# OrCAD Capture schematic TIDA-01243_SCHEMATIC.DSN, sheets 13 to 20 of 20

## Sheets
13 PAGE13_DP4320: size B; title: TIDA-01243: DP4320; rev: B
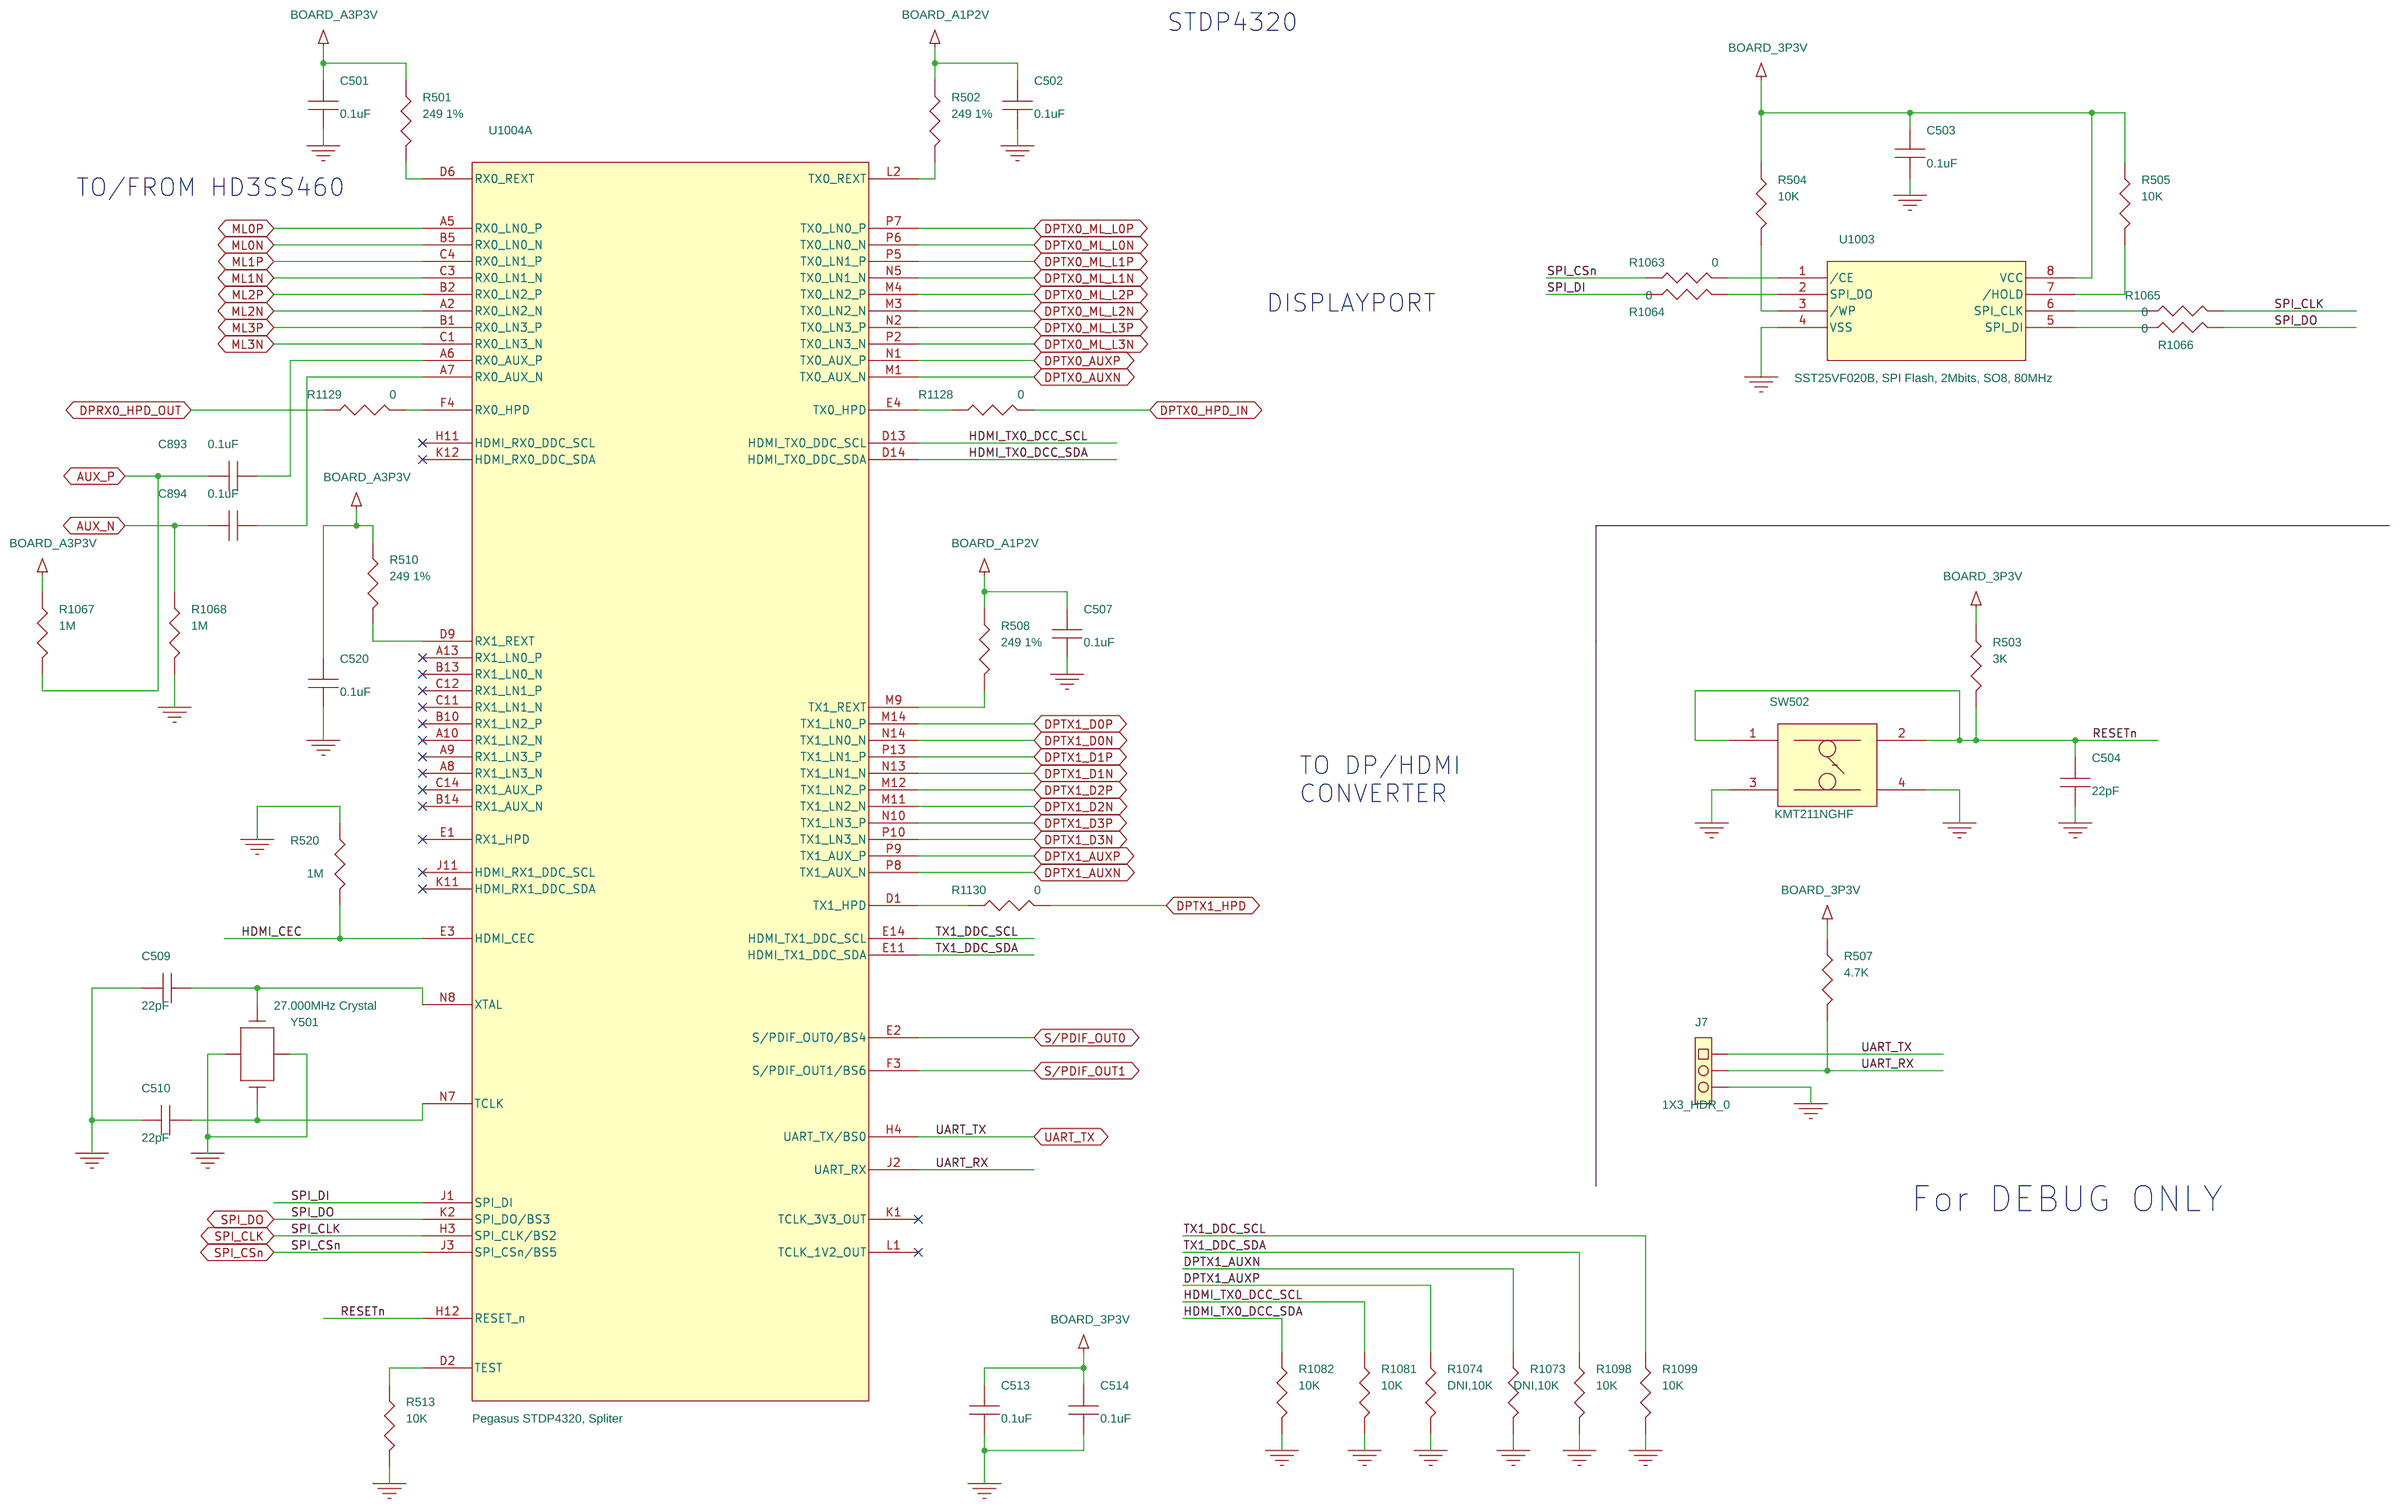
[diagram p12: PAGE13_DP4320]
14 PAGE14_DP4320_POWER: size B; title: TIDA-01243: DP4320 POWER; rev: B
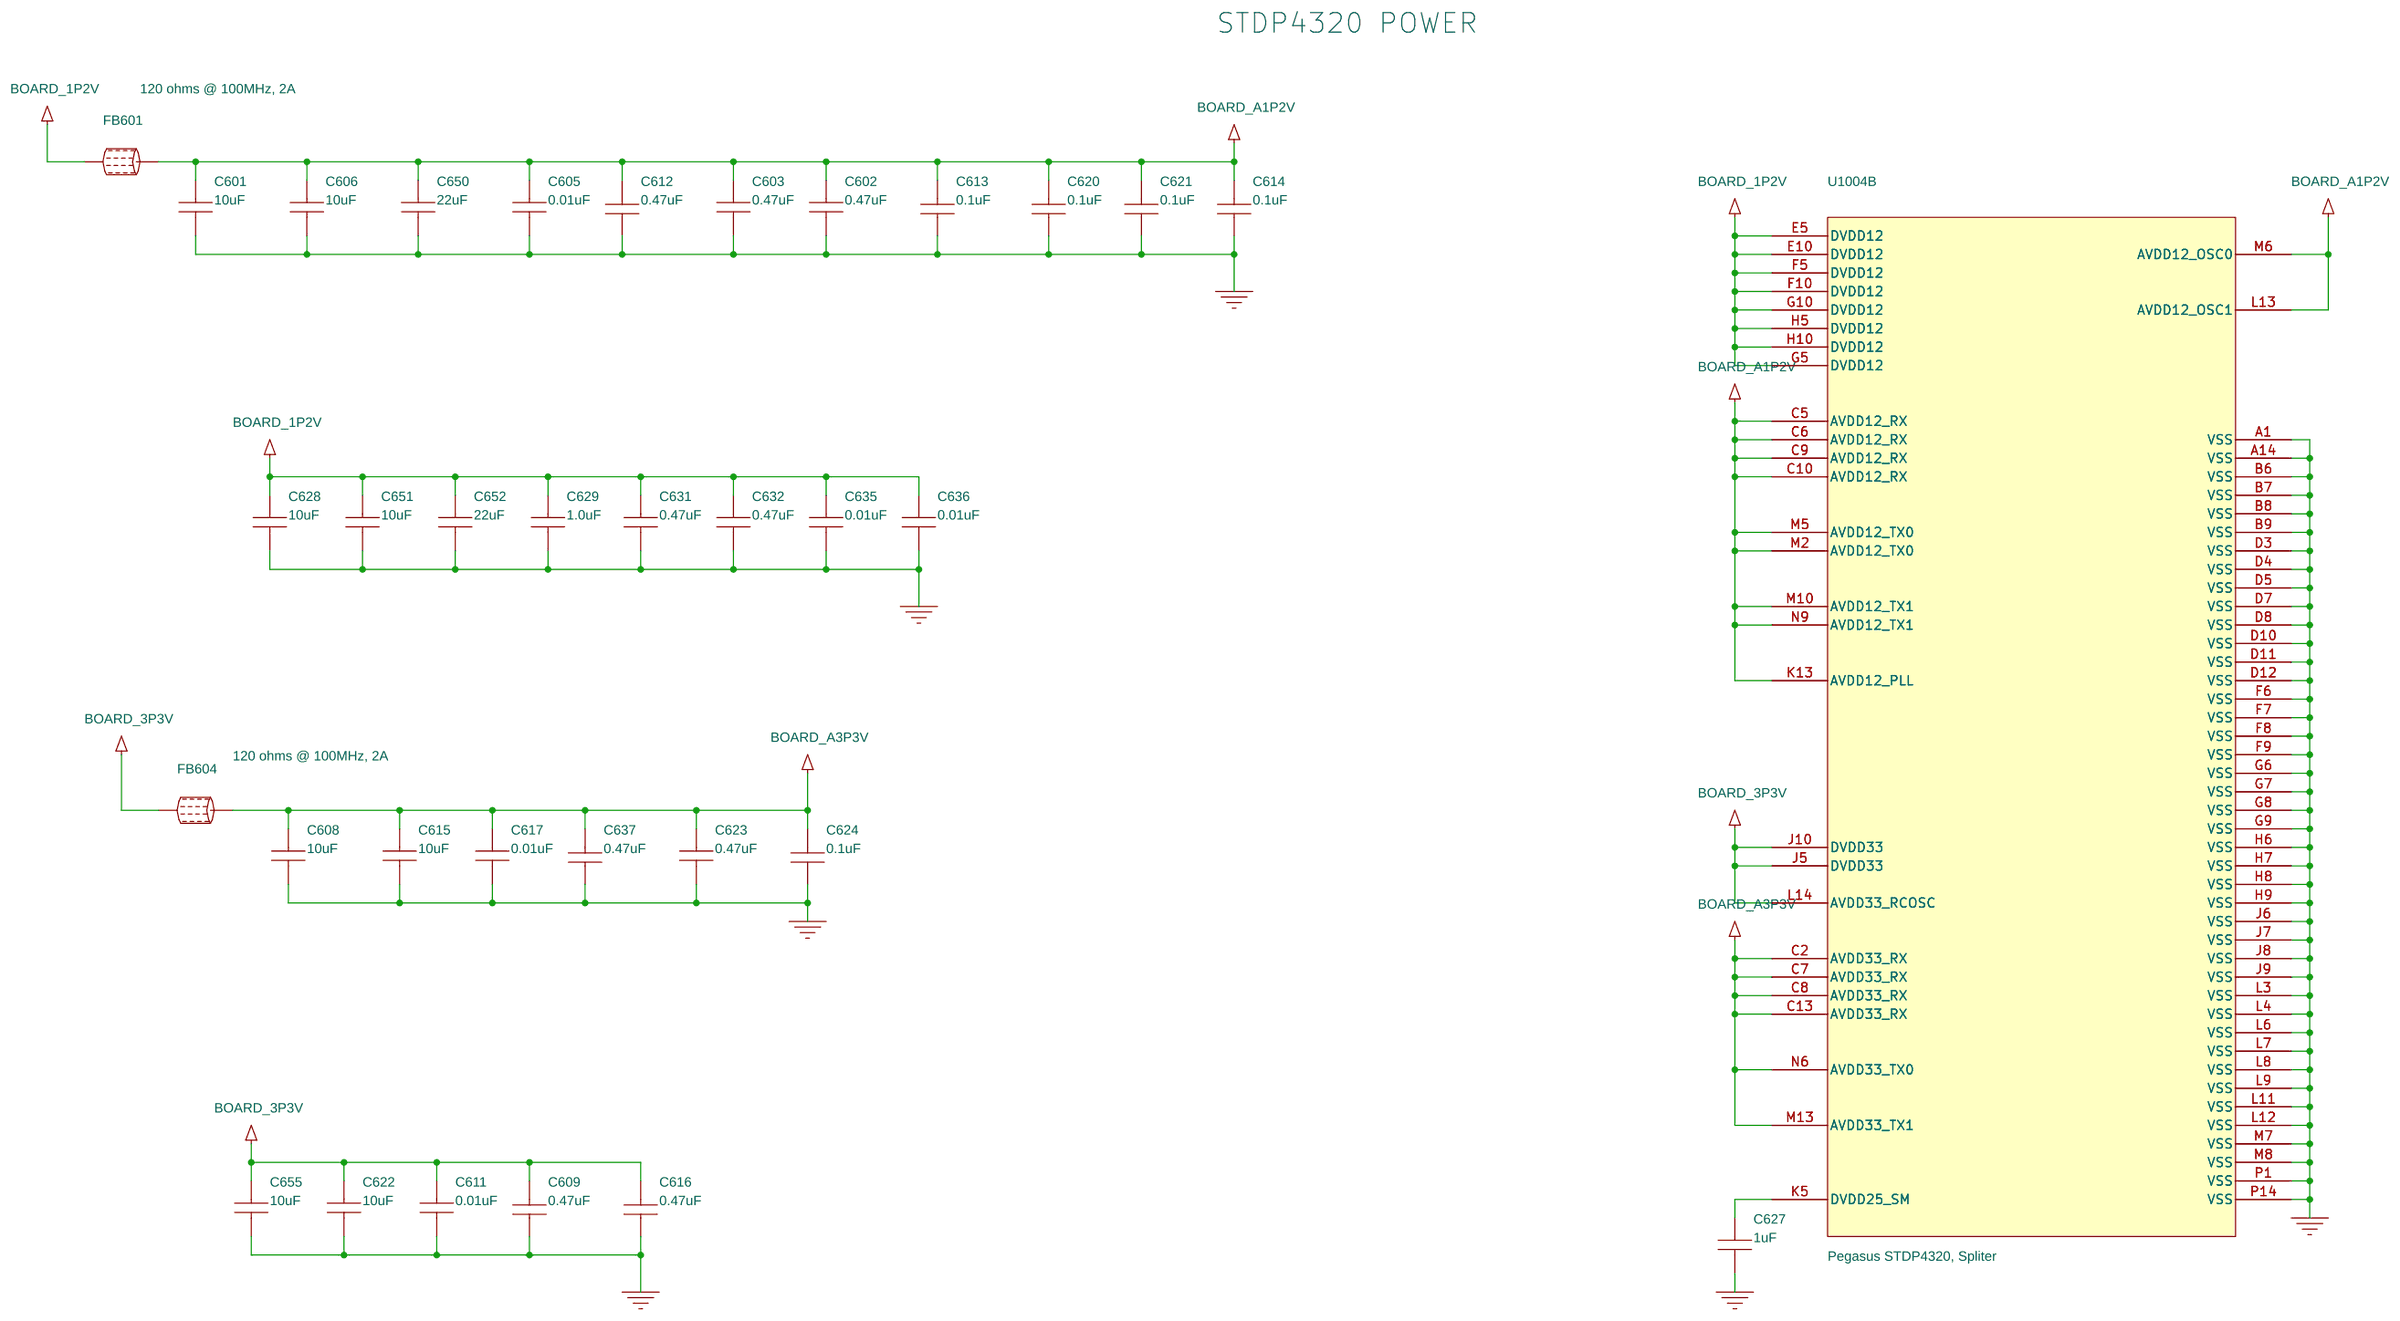
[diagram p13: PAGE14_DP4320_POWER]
15 PAGE15_DP4320_BOOTSTRAP: size B; title: TIDA-01243: DP4320 BOOTSTRAP; rev: B
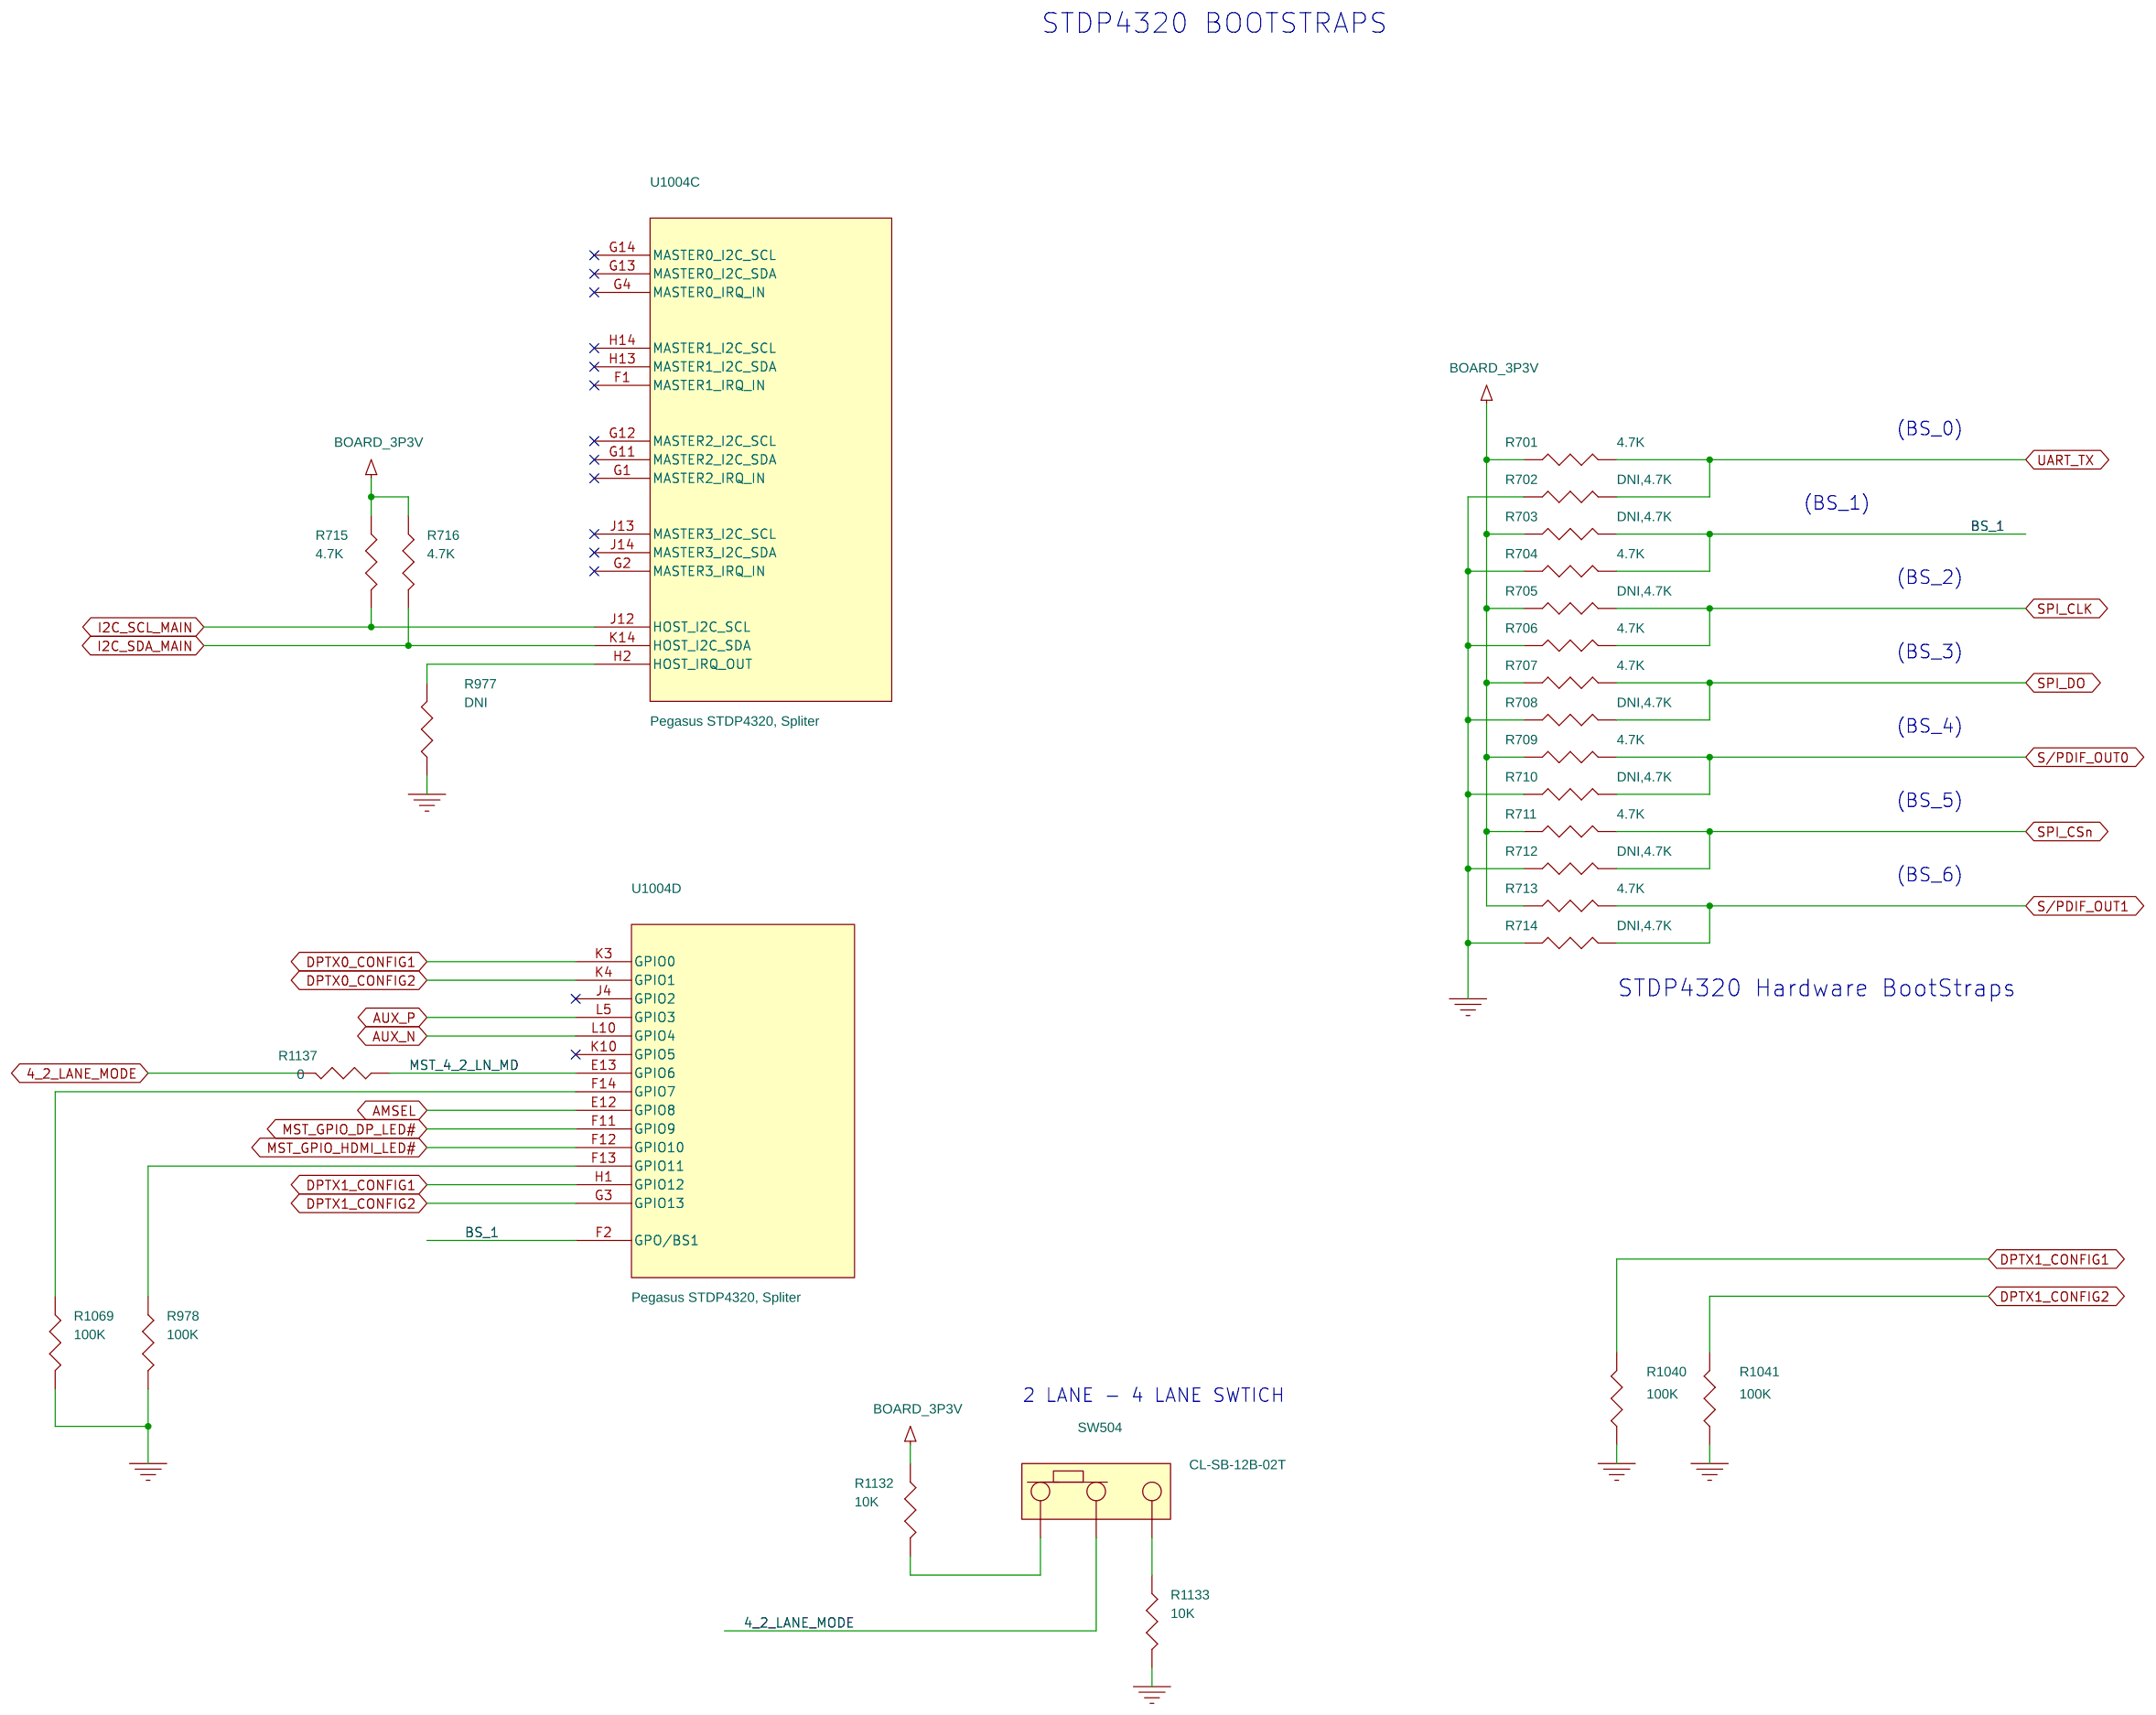
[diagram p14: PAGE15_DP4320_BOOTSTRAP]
16 PAGE16_DISPLAYPORT: size B; title: TIDA-01243: DISPLAY PORT; rev: B
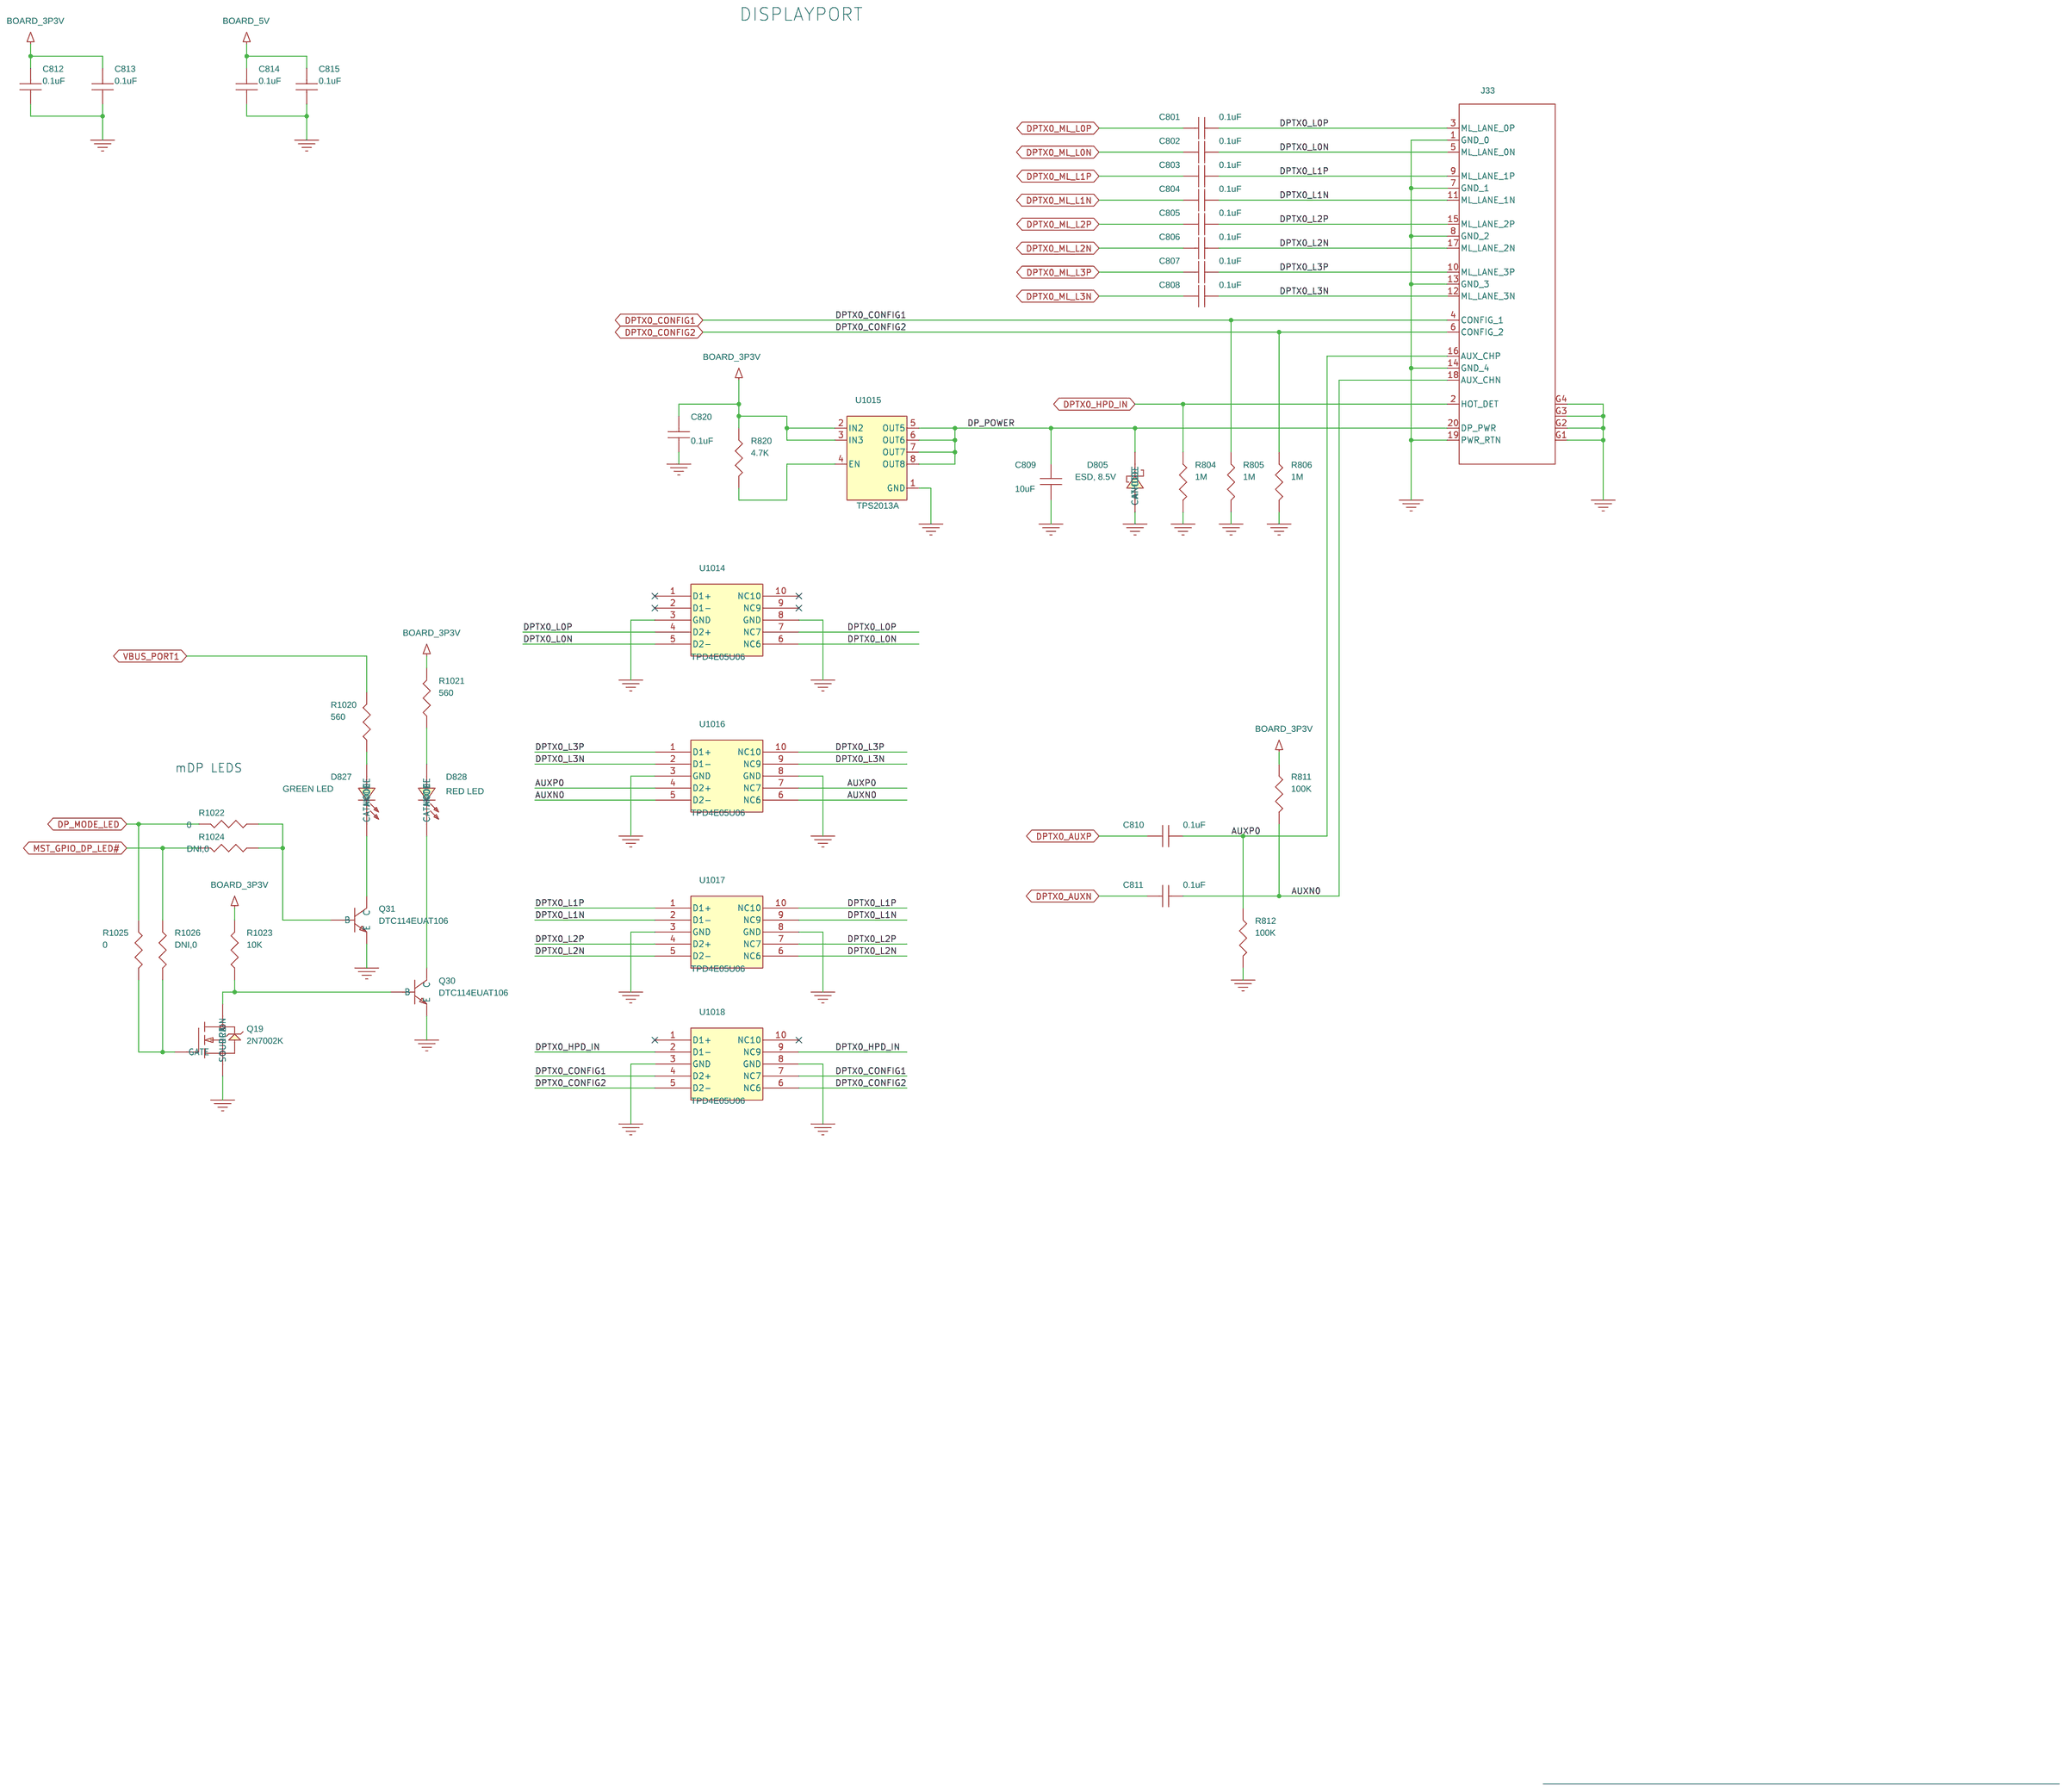
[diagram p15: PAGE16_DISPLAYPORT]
17 PAGE17_DP_TO_HDMI: size B; title: TIDA-01243: dDP TO HDMI; rev: B
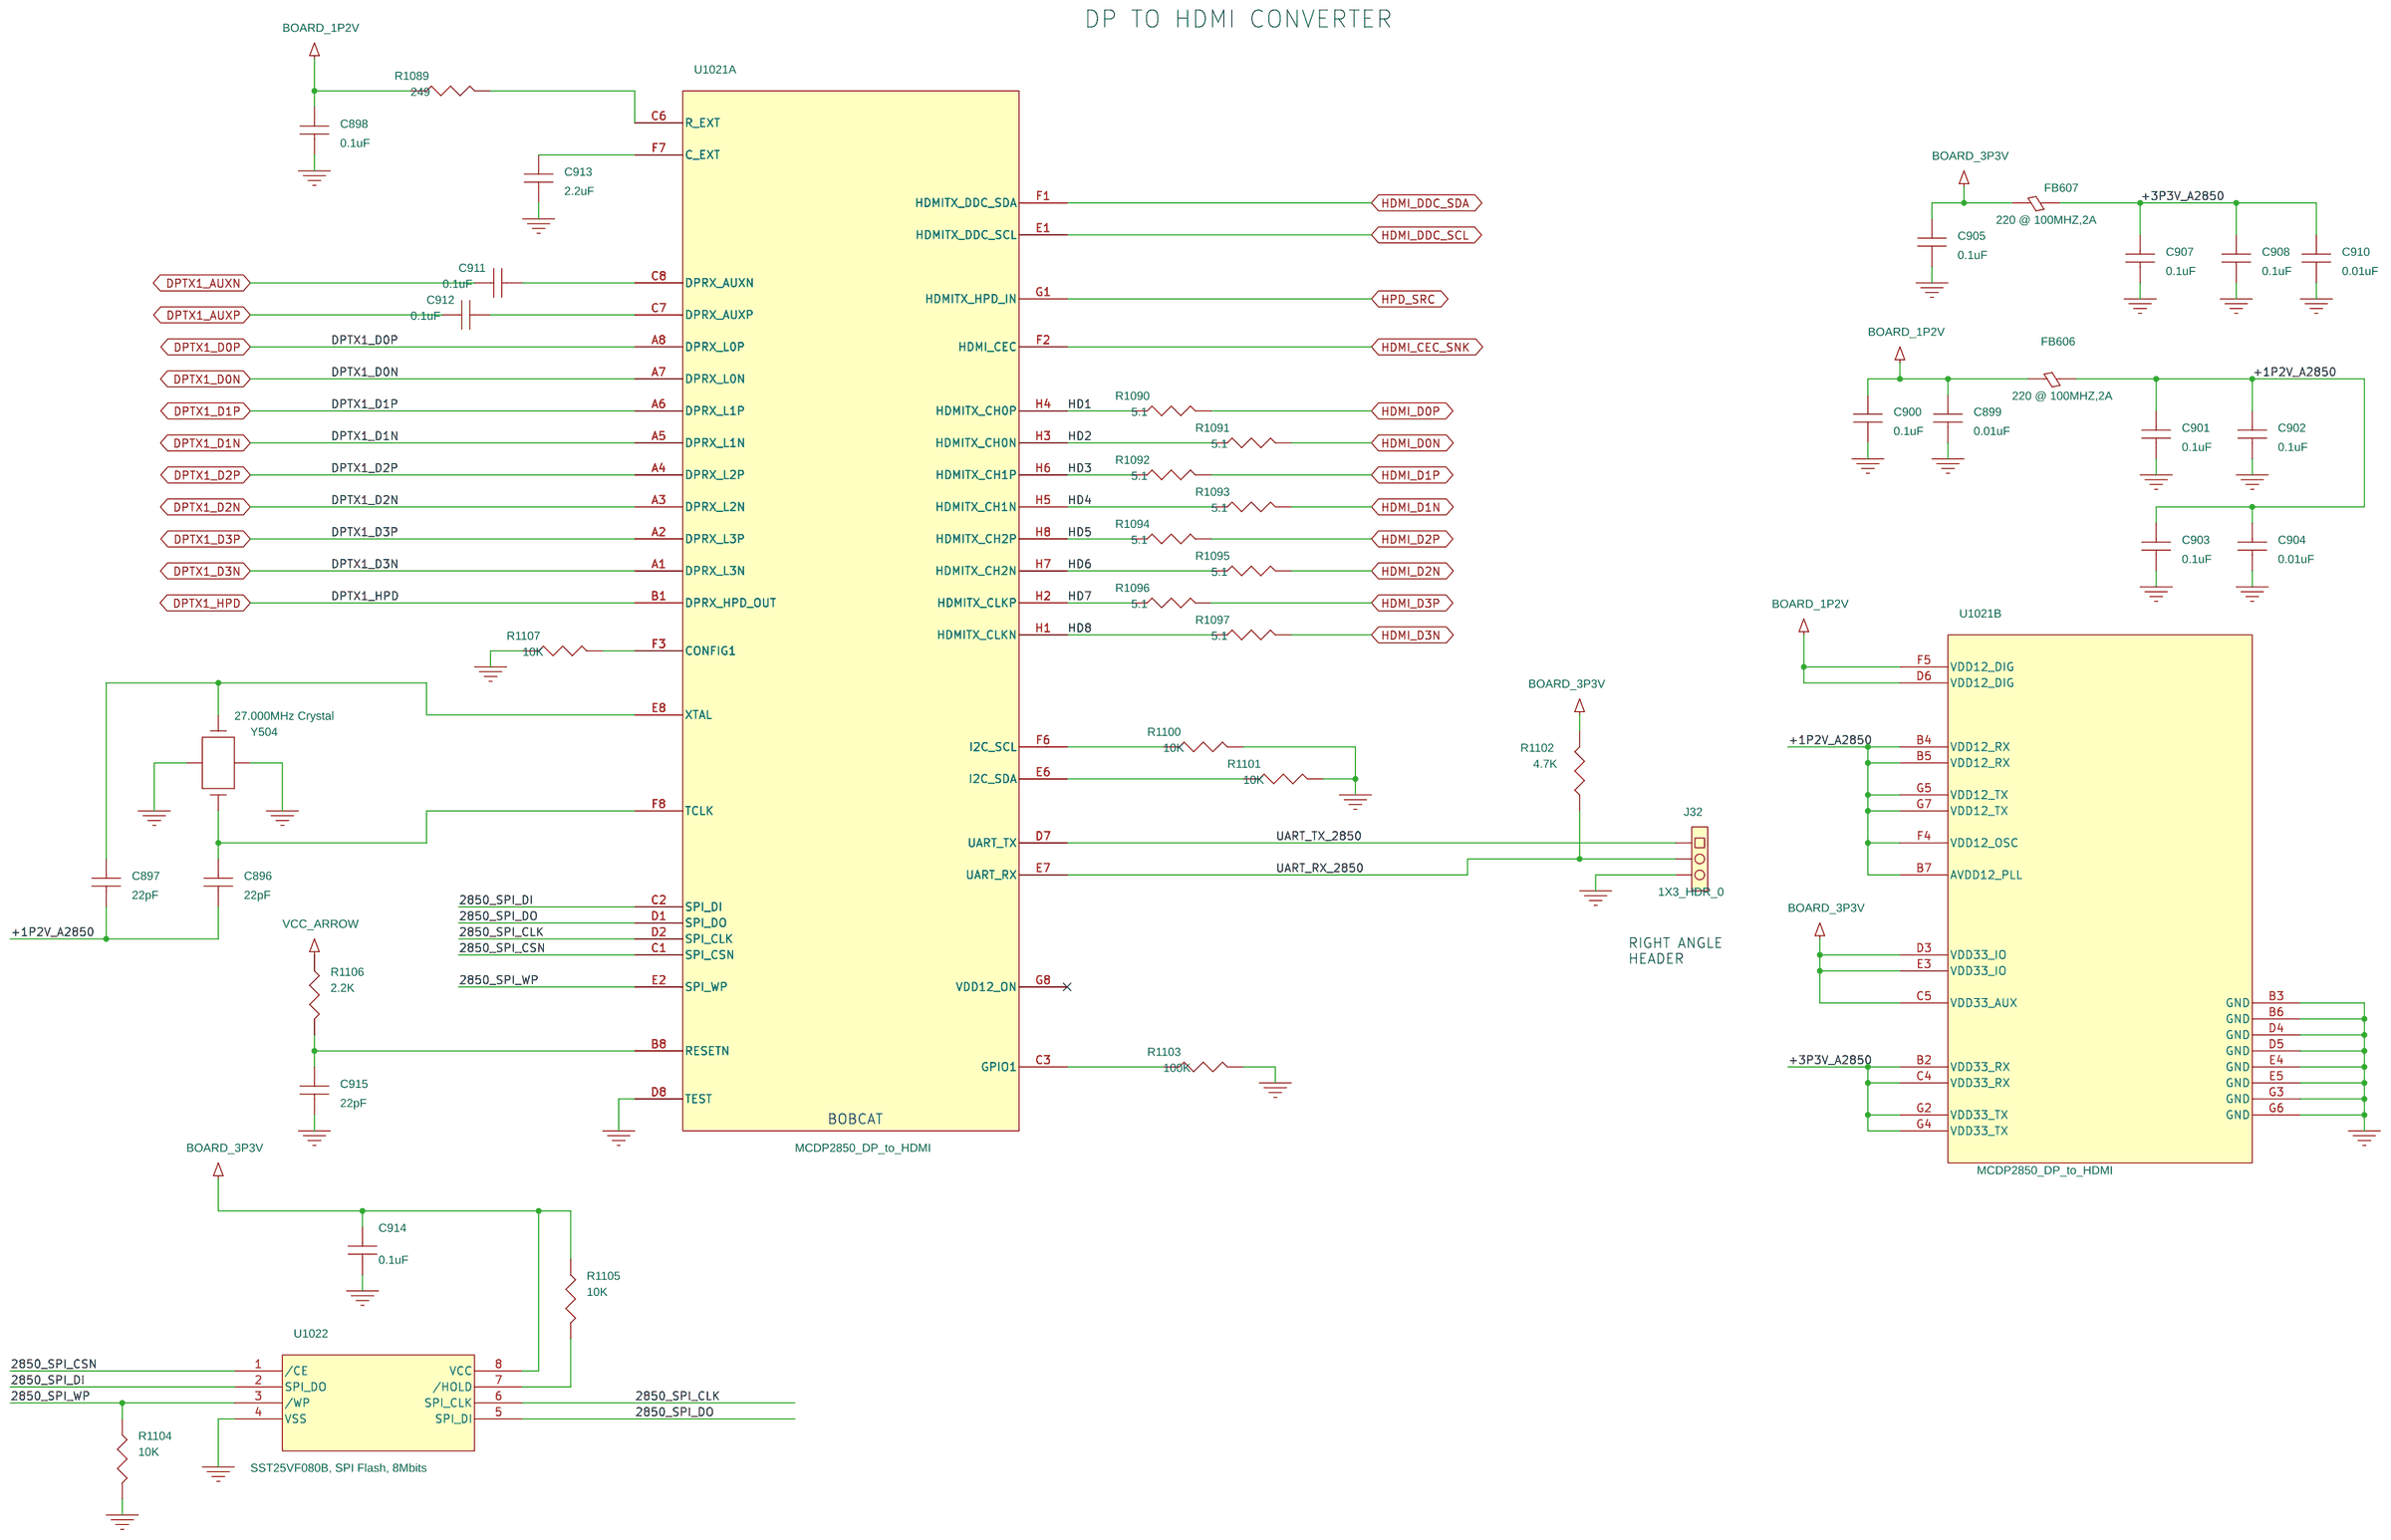
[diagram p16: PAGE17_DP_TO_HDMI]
18 PAGE18_HDMI_CONNECTOR: size B; title: TIDA-01243: HDMI CONNECTOR; rev: B
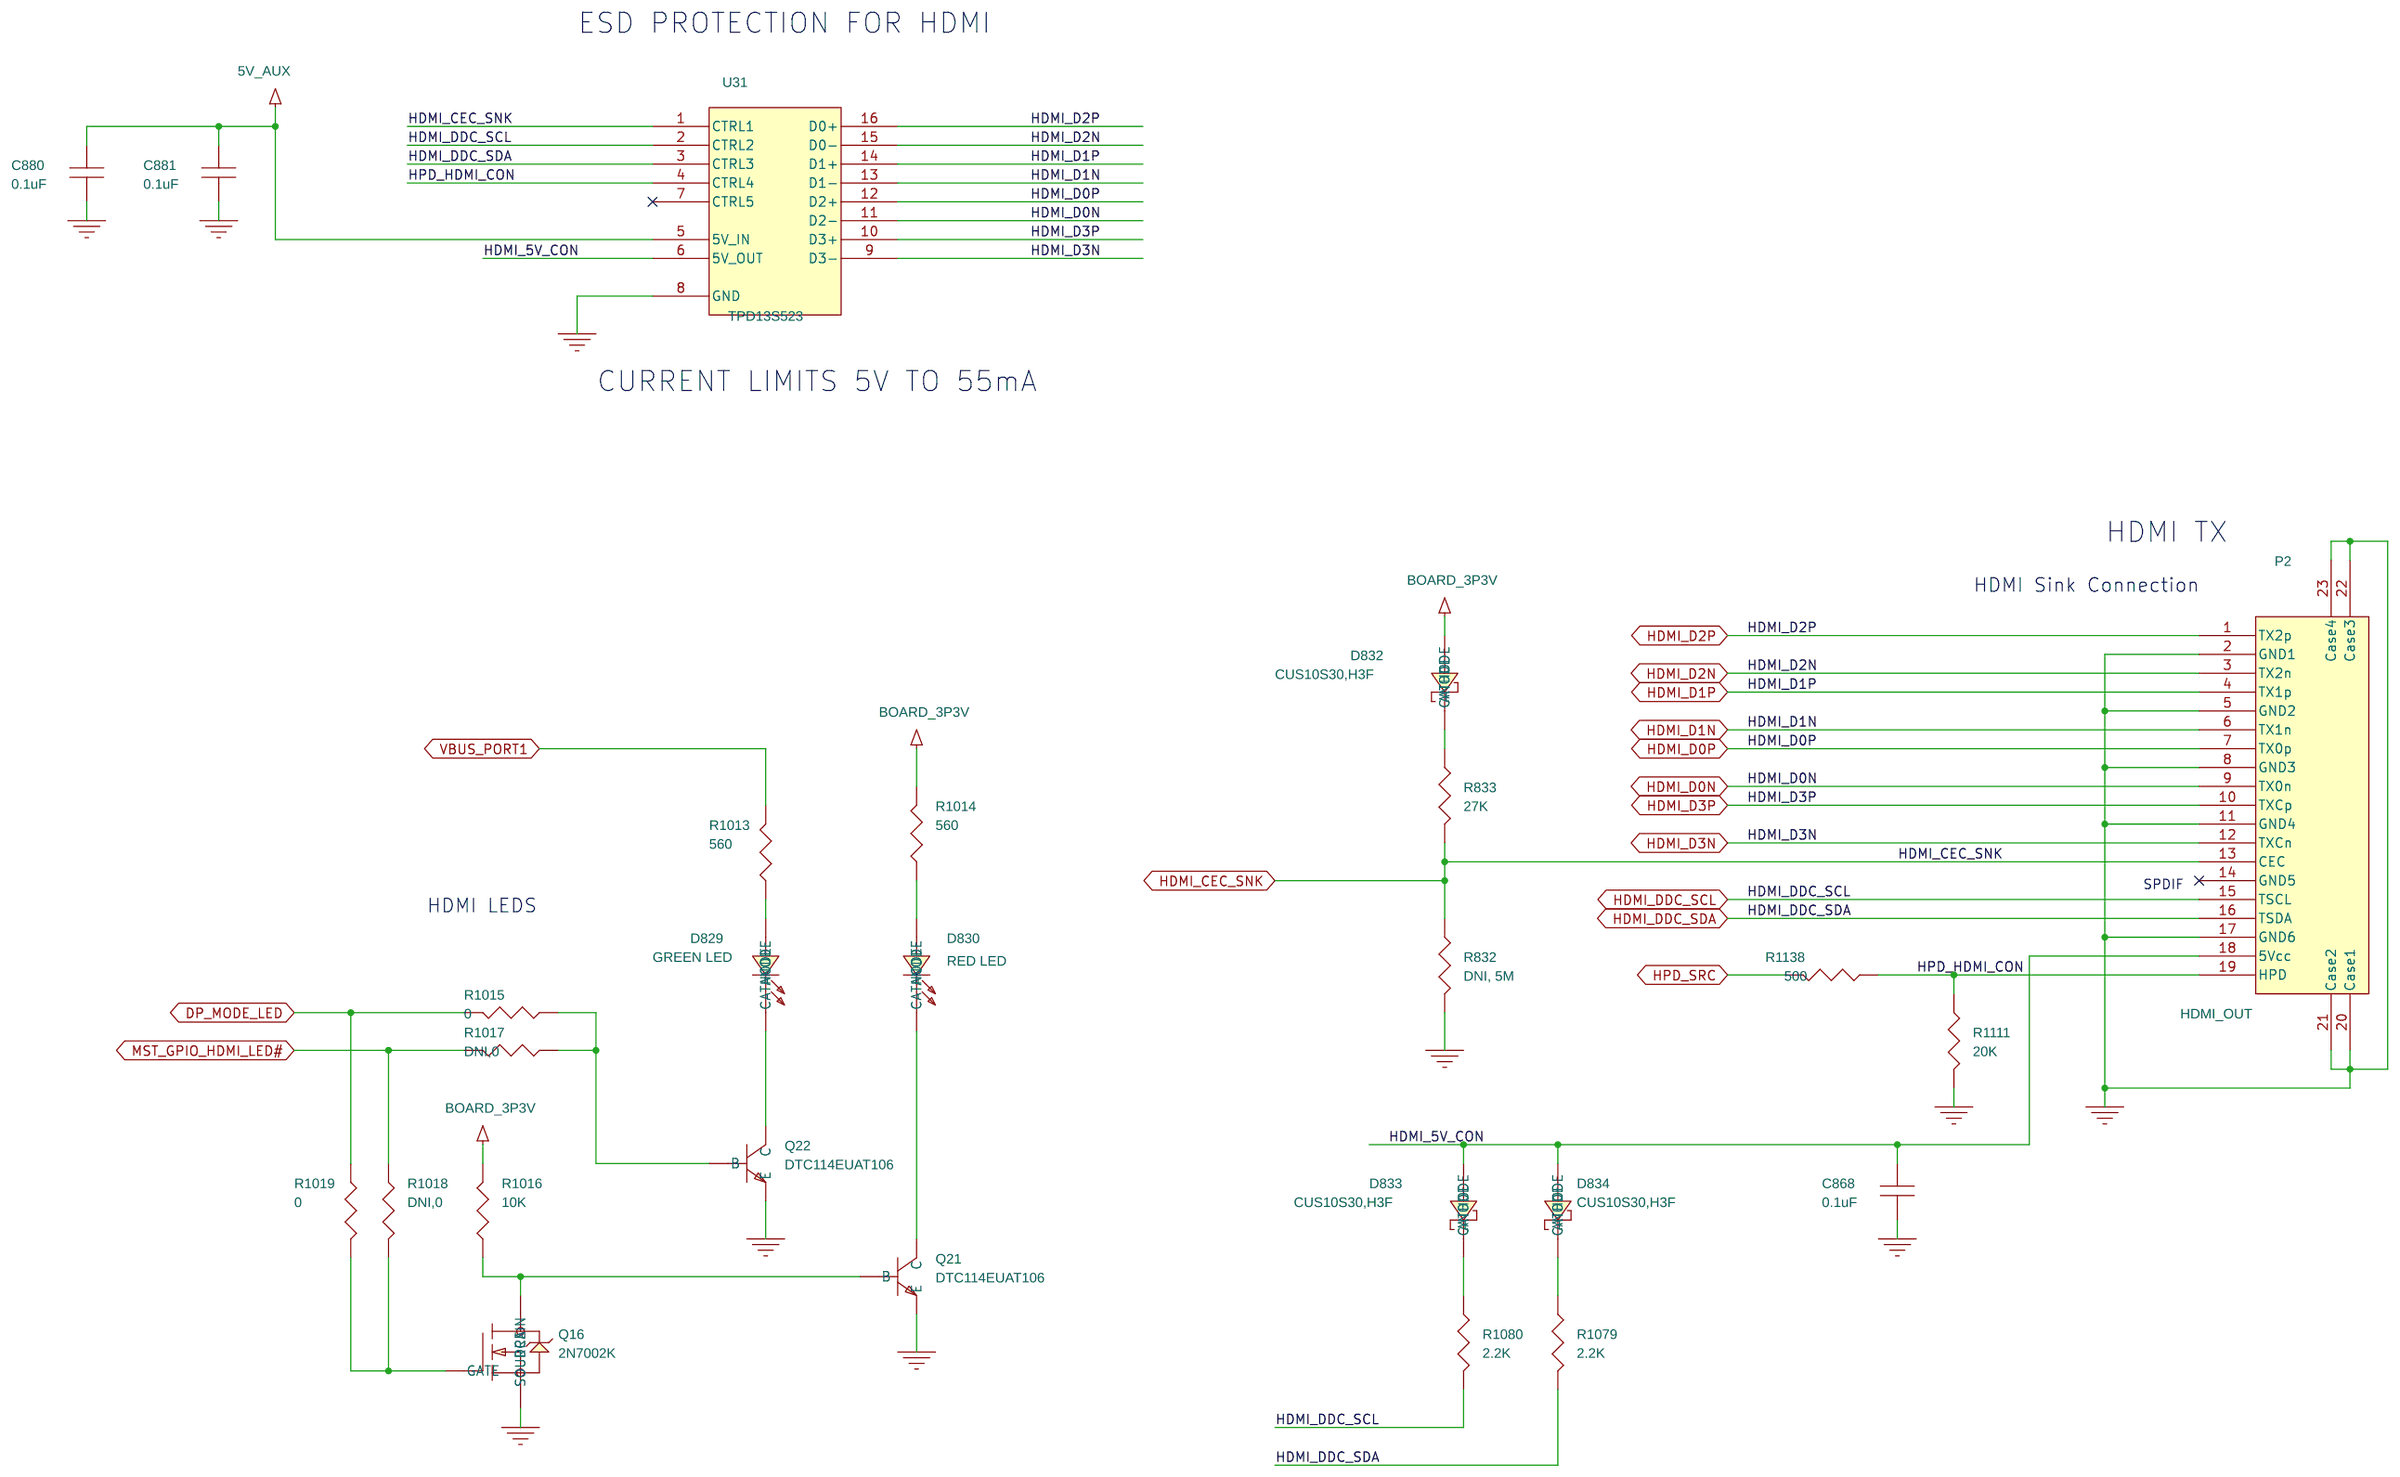
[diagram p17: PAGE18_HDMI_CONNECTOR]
19 PAGE19_DEBUG_BOARD: size B; title: TIDA-01243: Debug Board; rev: B
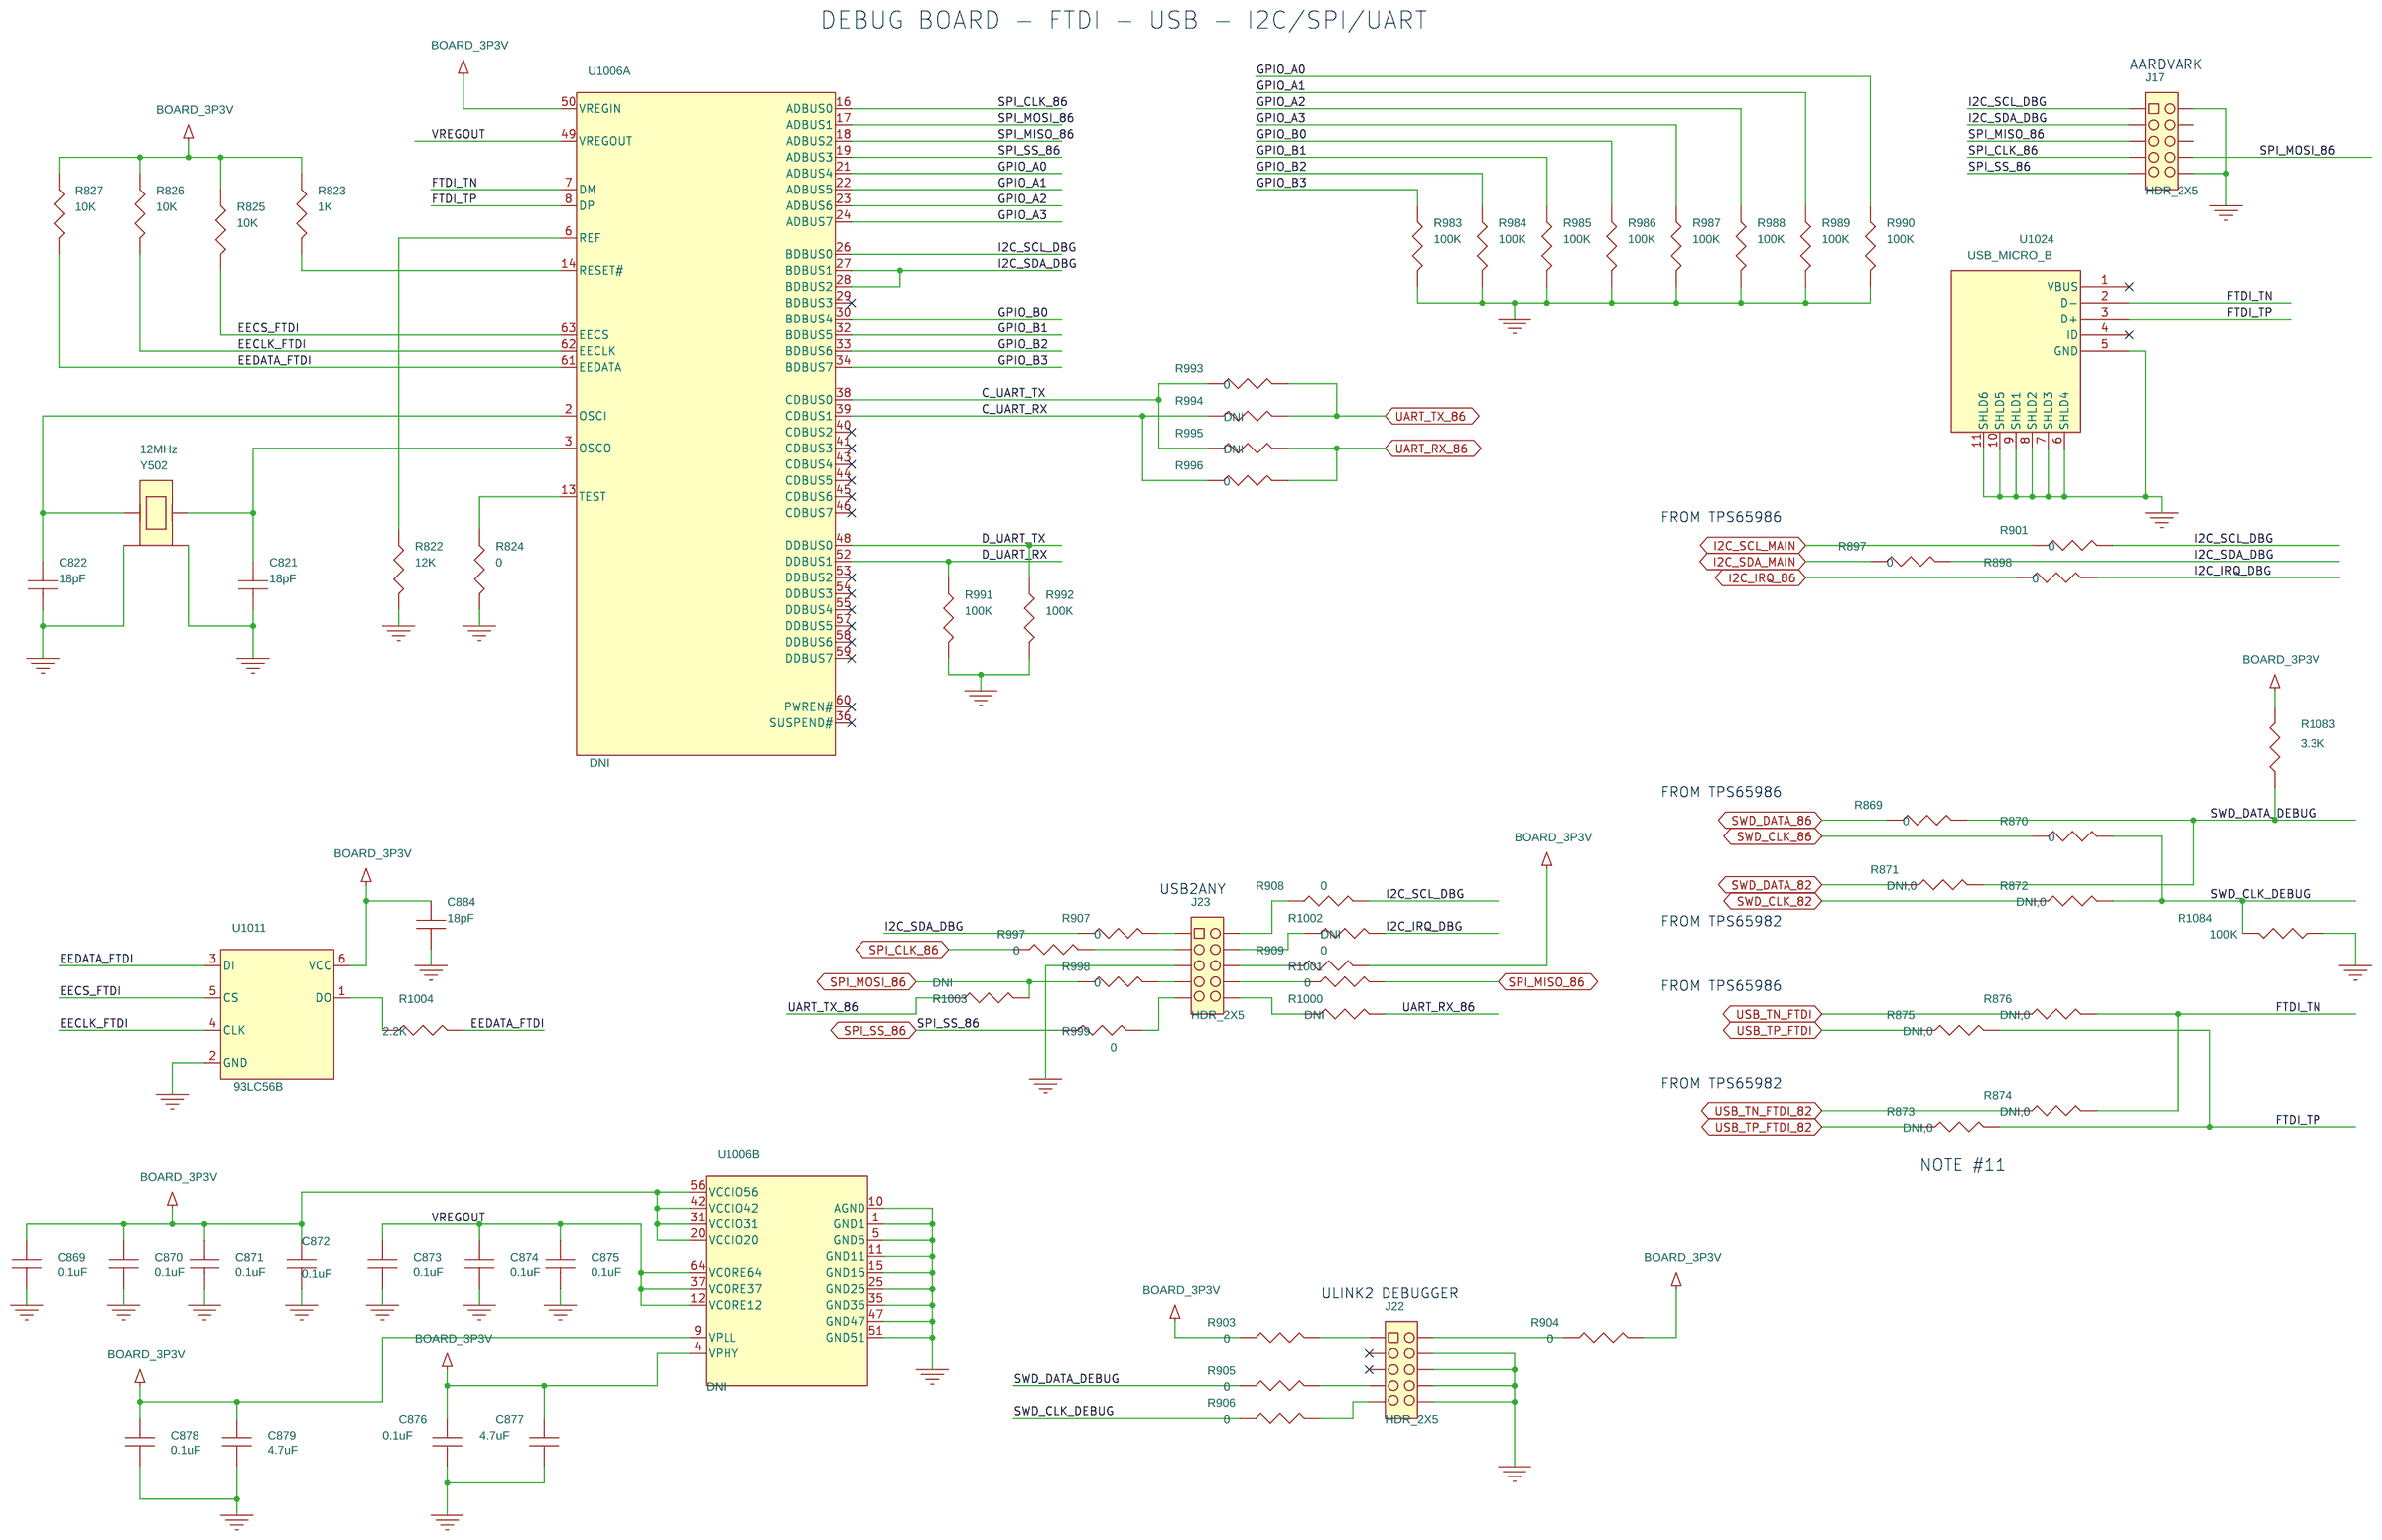
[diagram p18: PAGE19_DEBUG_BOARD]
20 PAGE04_USB_TYPEC_UP/HD3SS460: size B; title: TIDA-01243: USB TYPE-C; rev: B
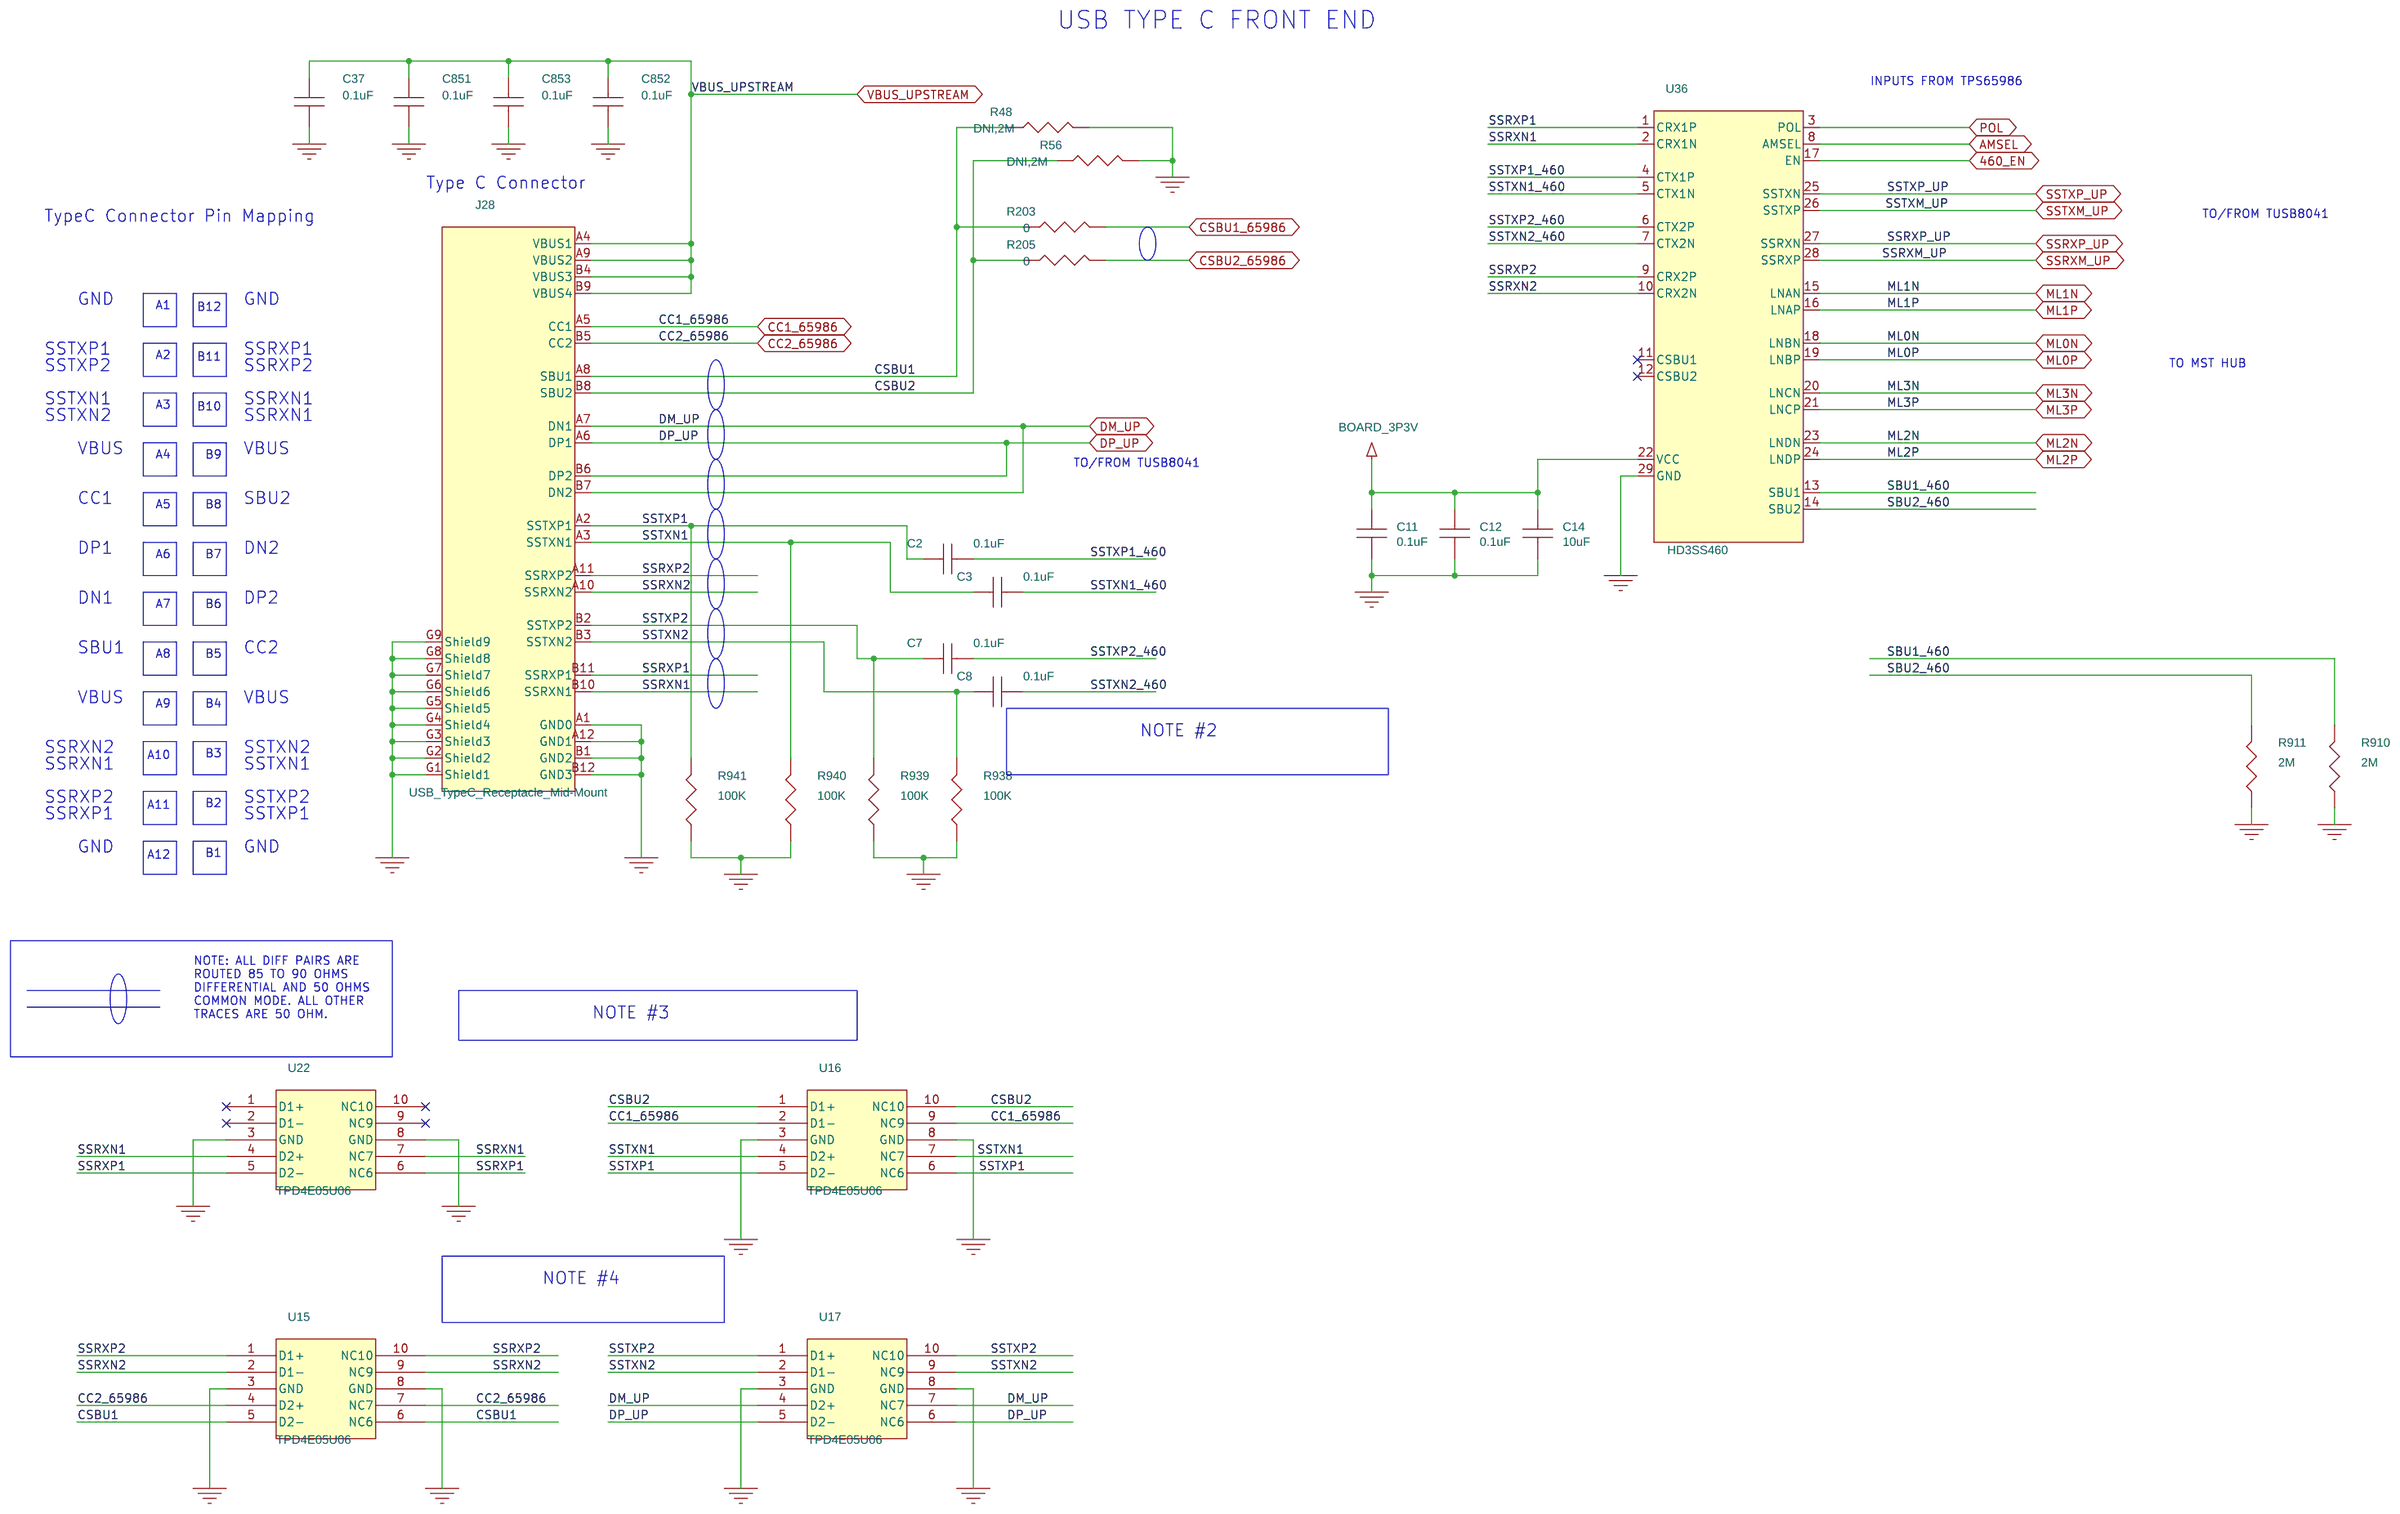
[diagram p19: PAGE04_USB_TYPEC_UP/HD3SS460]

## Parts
sheet PAGE04_USB_TYPEC_UP/HD3SS460
C2  0.1uF  [0201RND]
C3  0.1uF  [0201RND]
C7  0.1uF  [0201RND]
C8  0.1uF  [0201RND]
C11  0.1uF  [C0402]
C12  0.1uF  [C0402]
C14  10uF  [C0402]
C37  0.1uF  [C0402]
C851  0.1uF  [C0402]
C852  0.1uF  [C0402]
C853  0.1uF  [C0402]
J28  USB_TypeC_Receptacle_Mid-Mount  [USB_typeC_20-0000016-01]
R48  DNI,2M  [0201RND]
R56  DNI,2M  [0201RND]
R203  0  [0201RND]
R205  0  [0201RND]
R910  2M  [R0402]
R911  2M  [R0402]
R938  100K  [0201RND]
R939  100K  [0201RND]
R940  100K  [0201RND]
R941  100K  [0201RND]
U15  TPD4E05U06  [DQA]
U16  TPD4E05U06  [DQA]
U17  TPD4E05U06  [DQA]
U22  TPD4E05U06  [DQA]
U36  HD3SS460  [RHR_R-PWQFN-N28]
sheet PAGE13_DP4320
C501  0.1uF  [C0402]
C502  0.1uF  [C0402]
C503  0.1uF  [C0402]
C504  22pF  [C0402]
C507  0.1uF  [C0402]
C509  22pF  [C0402]
C510  22pF  [C0402]
C513  0.1uF  [C0402]
C514  0.1uF  [C0402]
C520  0.1uF  [C0402]
C893  0.1uF  [C0402]
C894  0.1uF  [C0402]
J7  1X3_HDR_0  [HDR_THVT_1X3_100]
R501  249 1%  [R0402]
R502  249 1%  [R0402]
R503  3K  [R0402]
R504  10K  [R0402]
R505  10K  [R0402]
R507  4.7K  [R0603]
R508  249 1%  [R0402]
R510  249 1%  [R0402]
R513  10K  [R0402]
R520  1M  [R0603]
R1063  0  [R0402]
R1064  0  [R0402]
R1065  0  [R0402]
R1066  0  [R0402]
R1067  1M  [R0402]
R1068  1M  [R0402]
R1073  DNI,10K  [R0402]
R1074  DNI,10K  [R0402]
R1081  10K  [R0402]
R1082  10K  [R0402]
R1098  10K  [R0402]
R1099  10K  [R0402]
R1128  0  [R0402]
R1129  0  [R0402]
R1130  0  [R0402]
SW502  KMT211NGHF  [SW_SMVT_KTM2]
U1003  SST25VF020B, SPI Flash, 2Mbits, SO8, 80MHz  [SOIC_8_197x157_50]
Y501  27.000MHz Crystal  [XTAL_4_SM_ECX-32]
sheet PAGE14_DP4320_POWER
C601  10uF  [C0603]
C602  0.47uF  [C0402]
C603  0.47uF  [C0402]
C605  0.01uF  [C0402]
C606  10uF  [C0603]
C608  10uF  [C0603]
C609  0.47uF  [C0402]
C611  0.01uF  [C0402]
C612  0.47uF  [C0402]
C613  0.1uF  [C0402]
C614  0.1uF  [C0402]
C615  10uF  [C0603]
C616  0.47uF  [C0402]
C617  0.01uF  [C0402]
C620  0.1uF  [C0402]
C621  0.1uF  [C0402]
C622  10uF  [C0603]
C623  0.47uF  [C0402]
C624  0.1uF  [C0402]
C627  1uF  [C0402]
C628  10uF  [C0603]
C629  1.0uF  [C0402]
C631  0.47uF  [C0402]
C632  0.47uF  [C0402]
C635  0.01uF  [C0402]
C636  0.01uF  [C0402]
C637  0.47uF  [C0402]
C650  22uF  [C0603]
C651  10uF  [C0603]
C652  22uF  [C0603]
C655  10uF  [C0603]
FB601  120 ohms @ 100MHz, 2A  [FB_0603]
FB604  120 ohms @ 100MHz, 2A  [FB_0603]
sheet PAGE15_DP4320_BOOTSTRAP
R701  4.7K  [R0402]
R702  DNI,4.7K  [R0402]
R703  DNI,4.7K  [R0402]
R704  4.7K  [R0402]
R705  DNI,4.7K  [R0402]
R706  4.7K  [R0402]
R707  4.7K  [R0402]
R708  DNI,4.7K  [R0402]
R709  4.7K  [R0402]
R710  DNI,4.7K  [R0402]
R711  4.7K  [R0402]
R712  DNI,4.7K  [R0402]
R713  4.7K  [R0402]
R714  DNI,4.7K  [R0402]
R715  4.7K  [R0402]
R716  4.7K  [R0402]
R977  DNI  [R0402]
R978  100K  [R0402]
R1040  100K  [R0402]
R1041  100K  [R0402]
R1069  100K  [R0402]
R1132  10K  [R0402]
R1133  10K  [R0402]
R1137  0  [R0402]
SW504  CL-SB-12B-02T  [SW_SMVT_CL-SB-12B-02]
U1004  Pegasus STDP4320, Spliter  [BGA_172_472X472_p80mm]  (sections A,B,C,D)
sheet PAGE16_DISPLAYPORT
C801  0.1uF  [C0402]
C802  0.1uF  [C0402]
C803  0.1uF  [C0402]
C804  0.1uF  [C0402]
C805  0.1uF  [C0402]
C806  0.1uF  [C0402]
C807  0.1uF  [C0402]
C808  0.1uF  [C0402]
C809  10uF  [C0603]
C810  0.1uF  [C0402]
C811  0.1uF  [C0402]
C812  0.1uF  [C0402]
C813  0.1uF  [C0402]
C814  0.1uF  [C0402]
C815  0.1uF  [C0402]
C820  0.1uF  [C0402]
D805  ESD, 8.5V  [Diode_ST0201]
D827  GREEN LED  [LED_0603]
D828  RED LED  [LED_0603]
J33  MINI_DISPLAY_PORT  [CON_RT_20_MINI_DP_JAE]
Q19  2N7002K  [SOT_23_321]
Q30  DTC114EUAT106  [SOT_323-312]
Q31  DTC114EUAT106  [SOT_323-312]
R804  1M  [R0603]
R805  1M  [R0603]
R806  1M  [R0603]
R811  100K  [R0402]
R812  100K  [R0402]
R820  4.7K  [R0402]
R1020  560  [R0402]
R1021  560  [R0402]
R1022  0  [R0402]
R1023  10K  [R0402]
R1024  DNI,0  [R0402]
R1025  0  [R0402]
R1026  DNI,0  [R0402]
U1014  TPD4E05U06  [DQA]
U1015  TPS2013A  [SOIC8]
U1016  TPD4E05U06  [DQA]
U1017  TPD4E05U06  [DQA]
U1018  TPD4E05U06  [DQA]
sheet PAGE17_DP_TO_HDMI
C896  22pF  [C0402]
C897  22pF  [C0402]
C898  0.1uF  [C0402]
C899  0.01uF  [C0402]
C900  0.1uF  [C0402]
C901  0.1uF  [C0402]
C902  0.1uF  [C0402]
C903  0.1uF  [C0402]
C904  0.01uF  [C0402]
C905  0.1uF  [C0402]
C907  0.1uF  [C0402]
C908  0.1uF  [C0402]
C910  0.01uF  [C0402]
C911  0.1uF  [C0402]
C912  0.1uF  [C0402]
C913  2.2uF  [C0402]
C914  0.1uF  [C0402]
C915  22pF  [C0402]
FB606  220 @ 100MHZ,2A  [FB_0603]
FB607  220 @ 100MHZ,2A  [FB_0603]
J32  1X3_HDR_0  [HDR_THVT_1X3_100]
R1089  249  [R0402]
R1090  5.1  [0201RND]
R1091  5.1  [0201RND]
R1092  5.1  [0201RND]
R1093  5.1  [0201RND]
R1094  5.1  [0201RND]
R1095  5.1  [0201RND]
R1096  5.1  [0201RND]
R1097  5.1  [0201RND]
R1100  10K  [R0402]
R1101  10K  [R0402]
R1102  4.7K  [R0603]
R1103  100K  [R0402]
R1104  10K  [R0402]
R1105  10K  [R0402]
R1106  2.2K  [R0402]
R1107  10K  [R0402]
U1021  MCDP2850_DP_to_HDMI  [LFBGA_64_7x7_0p8mm]  (sections A,B)
U1022  SST25VF080B, SPI Flash, 8Mbits  [SOIC_8_197x157_50]
Y504  27.000MHz Crystal  [XTAL_4_SM_ECX-32]
sheet PAGE18_HDMI_CONNECTOR
C868  0.1uF  [C0402]
C880  0.1uF  [C0402]
C881  0.1uF  [C0402]
D829  GREEN LED  [LED_0603]
D830  RED LED  [LED_0603]
D832  CUS10S30,H3F  [DIODE_SOD323]
D833  CUS10S30,H3F  [DIODE_SOD323]
D834  CUS10S30,H3F  [DIODE_SOD323]
P2  HDMI_OUT  [con_hdmi_SD-47151-001]
Q16  2N7002K  [SOT_23_321]
Q21  DTC114EUAT106  [SOT_323-312]
Q22  DTC114EUAT106  [SOT_323-312]
R832  DNI, 5M  [R0402]
R833  27K  [R0402]
R1013  560  [R0402]
R1014  560  [R0402]
R1015  0  [R0402]
R1016  10K  [R0402]
R1017  DNI,0  [R0402]
R1018  DNI,0  [R0402]
R1019  0  [R0402]
R1079  2.2K  [R0402]
R1080  2.2K  [R0402]
R1111  20K  [R0402]
R1138  500  [R0402]
U31  TPD13S523  [PW_PDSO_16]
sheet PAGE19_DEBUG_BOARD
C821  18pF  [C0402]
C822  18pF  [C0402]
C869  0.1uF  [C0402]
C870  0.1uF  [C0402]
C871  0.1uF  [C0402]
C872  0.1uF  [C0402]
C873  0.1uF  [C0402]
C874  0.1uF  [C0402]
C875  0.1uF  [C0402]
C876  0.1uF  [C0402]
C877  4.7uF  [C0402]
C878  0.1uF  [C0402]
C879  4.7uF  [C0402]
C884  18pF  [C0402]
J17  HDR_2X5  [HDR_THVT_2X5_100_M]
J22  HDR_2X5  [HDR_THVT_2X5_100_M]
J23  HDR_2X5  [HDR_THVT_2X5_100_M]
R822  12K  [R0402]
R823  1K  [R0402]
R824  0  [R0402]
R825  10K  [R0402]
R826  10K  [R0402]
R827  10K  [R0402]
R869  0  [R0402]
R870  0  [R0402]
R871  DNI,0  [R0402]
R872  DNI,0  [R0402]
R873  DNI,0  [0201RND]
R874  DNI,0  [0201RND]
R875  DNI,0  [0201RND]
R876  DNI,0  [0201RND]
R897  0  [R0402]
R898  0  [R0402]
R901  0  [R0402]
R903  0  [R0402]
R904  0  [R0402]
R905  0  [R0402]
R906  0  [R0402]
R907  0  [R0402]
R908  0  [R0402]
R909  0  [R0402]
R983  100K  [R0402]
R984  100K  [R0402]
R985  100K  [R0402]
R986  100K  [R0402]
R987  100K  [R0402]
R988  100K  [R0402]
R989  100K  [R0402]
R990  100K  [R0402]
R991  100K  [R0603]
R992  100K  [R0603]
R993  0  [R0402]
R994  DNI  [R0402]
R995  DNI  [R0402]
R996  0  [R0402]
R997  0  [R0402]
R998  0  [R0402]
R999  0  [R0402]
R1000  DNI  [R0402]
R1001  0  [R0402]
R1002  DNI  [R0402]
R1003  DNI  [R0402]
R1004  2.2K  [R0402]
R1083  3.3K  [R0402]
R1084  100K  [R0402]
U1006  DNI  [QFP_64_10x10mm_0p5]  (sections A,B)
U1011  93LC56B  [SOT23_6]
U1024  USB_MICRO_B  [usb_smrt_micro_ab_Hirose]
Y502  12MHz  [XTAL_4_SM_2x2p5mm]

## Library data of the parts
C2 C3 C7 C8 C11 C12 C14 C821 C822 C884 = CAP_NP: 6.3V Capacitor
C37 C851-C853 = CAP_NP: 25V Capacitor
J28 = USBTypeC_Receptacle_TOPMount_0: MANUFACTURER: LINTES; MANUFACTURER'S PART NUMBER: AUSB0129; TI_SILKTEXT: UFP
R48 R56 R203 R205 R910 R911 R938-R941 R1013-R1026 R1040 R1041 R1089-R1097 R1100 R1101 R1103 R1107 = R
U15-U17 U22 U1014 U1016-U1018 = TPD4E05U06: MANUFACTURER'S PART NUMBER: TPD4E05U06DQAR
U36 = HD3SS460: MANUFACTURER: TEXAS INSTRUMENTS; MANUFACTURER'S PART NUMBER: HD3SS460RHRT
C501-C503 C507 C513 C514 C520 C893 C894 C914 = CAP_NP: Ceramic; Part Number: CDN-CAP-2013; Part Type: CAP
C504 C509 C510 C896-C905 C907 C908 C910-C913 C915 = CAP_NP: Ceramic; Part Number: CDN-CAP-2016
J7 J32 = 1X3_HDR_0
R501 R502 R508 R510 R1067 R1068 = R: 1%, 1/10W SMD Resistor; Part Number: CDN-RES-2032; Tolerance: 0.01
R503 = R: 1%, 1/10W SMD Resistor; Part Number: CDN-RES-2043; Tolerance: 0.01
R504 R505 R513 R822-R827 R869-R876 R897 R898 R901 R903-R909 R983-R1004 R1063-R1066 R1073 R1074 R1081-R1084 R1098 R1099 R1104-R1106 R1128-R1130 = R: 1%, 1/10W SMD Resistor; Part Number: CDN-RES-2026; Tolerance: 0.01
R507 R701-R716 R977 R978 R1069 R1102 R1132 R1133 = R: 1%, 1/10W SMD Resistor; Part Number: CDN-RES-2034; Tolerance: 0.01
R520 R804-R806 = R: 1%, 1/10W SMD Resistor; Part Number: CDN-RES-2031; Tolerance: 0.01
SW502 = KMT211GHF: MANUFACTURER: C&K; MANUFACTURER'S PART NUMBER: KMT211NGHFLFS; TI_SILKTEXT: VIDRST
U1003 = SPI_Flash: Manufacturer: Microchip technologies; Manufacturer's Part Number: SST25VF020B-80-4I-SAE; Part Number: CDN-IC-1050
Y501 Y504 = CRYSTAL_1: Manufacturer: ECS Inc; Manufacturer's Part Number: ECS-270-20-33-TR; Part Number: CDN-OSC-0025
C601 C606 C608 C615 C622 C628 C651 C655 = CAP_NP: Ceramic; Part Number: CDN-CAP-0002; Tolerance: 0.1
C602 C603 C623 C631 C632 = CAP_NP: Ceramic; Part Number: CDN-CAP-2015
C605 C611 C617 C635 C636 = CAP_NP: Ceramic; Part Number: CDN-CAP-2049; Tolerance: 0.1
C609 C612 C616 C637 = CAP_NP: Ceramic; Part Number: CDN-CAP-2015; Part Type: Ceramic
C613 C614 C620 C621 C624 C812-C815 C820 = CAP_NP: Ceramic; Part Number: CDN-CAP-2013; Part Type: Ceramic
C627 = CAP_NP: Ceramic; Part Number: CDN-CAP-2010
C629 = CAP_NP: Ceramic; Part Number: CDN-CAP-0001; Tolerance: 0.1
C650 C652 = CAP_NP: CAP CER 22uF 6.3V 20% X5R 0805; Part Number: CDN-CAP-2130
FB601 = FERRITE_BEAD: Manufacturer: Marata Electronics; Manufacturer's Part Number: BLM18PG121SN1D; Part Number: CDN-FER-0018
FB604 = FERRITE_BEAD: 3A 0.04R 30ohms@100MHz; Manufacturer: Marata Electronics; Manufacturer's Part Number: BLM18PG121SN1D; Part Number: CDN-FER-0018
R1137 R1138 = R: Resistor; Tolerance: 5%
SW504 = SLIDE_SWITCH: MANUFACTURER: COPAL ELECTRONICS
U1004 = STDP4320: FPLIST: ST/TFBGA8X8X1.2_196,ST/LFBGA12X12X1.7_196; Manufacturer: MegaChips; Part Number: CDN-IC-1031
C801-C808 C810 C811 = CAP_NP: Ceramic; Part Number: CDN-CAP-2013
C809 = CAP_NP: CAP CER 47uF 6.3V 20% X5R 1206; Part Number: CDN-CAP-2080
D805 = DIODE-SCHOTTKY-SK32_0: Manufacturer: STMicroelectronics; Manufacturer's Part Number: ESDAVLC8-1BU2; Part Number: CDN-ESD-0027
D827 = LED_0: MANUFACTURER: LITE-ON; MANUFACTURER'S PART NUMBER: LTST-C191GKT; TI_SILKTEXT: MSTMD
D828 = LED_0: MANUFACTURER: LITE-ON; MANUFACTURER'S PART NUMBER: LTST-C190EKT; TI_SILKTEXT: MSTMD
J33 = MINI_DISPLAY_PORT_SOURCE: MANUFACTURER: JAE; MANUFACTURER'S PART NUMBER: DP3AR020SU32JQ1
Q16 Q19 = 2N7002_1: Manufacturer: VISHAY; Manufacturer's Part Number: 2N7002K-T1-E3
Q21 Q22 Q30 Q31 = DTC114EUAT106: MANUFACTURER: Rohm Semi; Manufacturer Part Number: DTC114EAUT106
R811 R812 = R: 1%, 1/10W SMD Resistor; Part Number: CDN-RES-2022; Tolerance: 0.01
R820 = R: RES 4.70K OHM 1/10W 1% 0402 SMD; Part Number: CDN-RES-2076; Tolerance: 0.01
U1015 = TPS2013A: MANUFACTURER: TEXAS INSTRUMENTS; MANUFACTURER'S PART NUMBER: TPS2013AD
FB606 FB607 = FERRITE_BEAD_v2: Ferrite Bead; Digi-Key Part Number: 490-3992-1-ND; Manufacturer: MuRata; Manufacturer's Part Number: BLM18EG221SN1D
U1021 = MCDP2850: Manufacturer: MegaChips
U1022 = SPI_Flash: Manufacturer: Microchip technologies; Manufacturer's Part Number: SST25VF080B-80-4I-SAE; Part Number: CDN-IC-1050
C868-C881 = CAP_NP
D829 = LED_0: MANUFACTURER: LITE-ON; MANUFACTURER'S PART NUMBER: LTST-C191GKT; TI_SILKTEXT: DPMD
D830 = LED_0: MANUFACTURER: LITE-ON; MANUFACTURER'S PART NUMBER: LTST-C190EKT; TI_SILKTEXT: DPMD
D832-D834 = DIODE_SCHOTTKY_0: MANUFACTURER: TOSHIBA
P2 = CONN_HDMI_TYPE_A_0: MANUFACTURER'S PART NUMBER: 471511001; Manuf: Molex; Manuf PN: 500254-1927; Manufacturer: Molex; SILKTEXT: HDMI OUT; TI_SILKTEXT: HDMI
R832 R833 R1079 R1080 R1111 = r0402
U31 = TPD13S523: MANUFACTURER: TEXAS INSTRUMENTS; MANUFACTURER'S PART NUMBER: TPD13S523PWR
J17 = HDR_2X5: TI_SILKTEXT: AARDVARK
J22 = HDR_2X5: TI_SILKTEXT: ULINK2
J23 = HDR_2X5: TI_SILKTEXT: USB2ANY
U1006 = FT4232H: MANUFACTURER: FTDI; MANUFACTURER'S PART NUMBER: FT4232HL
U1011 = 93LC56B: MANUFACTURER: MICROCHIP; MANUFACTURER'S PART NUMBER: 93LC56B-I/OT
U1024 = USB_MICRO_B: MANUFACTURER: Hirose; MANUFACTURER'S PART NUMBER: ZX62D-AB-5P8
Y502 = CRYSTAL_4_PIN: MANUFACTURER: TXC CORP; MANUFACTURER'S PART NUMBER: 8Z-12.000MAAJ-T

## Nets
5V_AUX: C880.1 C881.1 U31.5(5V_IN) ; also on sheet 6 7 10
GND: C11.2 C12.2 C14.2 C37.2 C501.1 C502.1 C503.2 C504.1 C507.1 C509.2 C510.1 C513.1 C514.1 C520.1 C601.2 C602.2 C603.2 C605.2 C606.2 C608.2 C609.1 C611.2 C612.1 C613.1 C614.1 C615.2 C616.1 C617.2 C620.1 C621.1 C622.2 C623.2 C624.1 C627.2 C628.2 C629.2 C631.2 C632.2 C635.2 C636.2 C637.1 C650.2 C651.2 C652.2 C655.2 C809.2 C812.1 C813.1 C814.1 C815.1 C820.1 C821.2 C822.2 C851.2 C852.2 C853.2 C868.2 C869.2 C870.2 C871.2 C872.2 C873.2 C874.2 C875.2 C876.2 C877.2 C878.2 C879.2 C880.2 C881.2 C884.2 C898.2 C899.2 C900.2 C901.2 C902.2 C903.2 C904.2 C905.2 C907.2 C908.2 C910.2 C913.2 C914.2 C915.2 D805.2(ANODE) J7.3 J17.2 J17.10 J22.4 J22.6 J22.8 J22.10 J23.5 J28.A1(GND0) J28.A12(GND1) J28.B1(GND2) J28.B12(GND3) J28.G1(Shield1) J28.G2(Shield2) J28.G3(Shield3) J28.G4(Shield4) J28.G5(Shield5) J28.G6(Shield6) J28.G7(Shield7) J28.G8(Shield8) J28.G9(Shield9) J32.3 J33.1(GND_0) J33.7(GND_1) J33.8(GND_2) J33.13(GND_3) J33.14(GND_4) J33.19(PWR_RTN) J33.G1 J33.G2 J33.G3 J33.G4 P2.2(GND1) P2.5(GND2) P2.8(GND3) P2.11(GND4) P2.17(GND6) P2.20(Case1) P2.21(Case2) P2.22(Case3) P2.23(Case4) Q16.2(SOURCE) Q19.2(SOURCE) Q21.1(E) Q22.1(E) Q30.1(E) Q31.1(E) R48.2 R56.2 R513.2 R520.1 R702.1 R704.1 R706.1 R708.1 R710.1 R712.1 R714.1 R804.2 R805.2 R806.2 R812.2 R822.2 R824.2 R832.2 R910.1 R911.1 R938.1 R939.1 R940.1 R941.1 R977.1 R978.2 R983.2 R984.2 R985.2 R986.2 R987.2 R988.2 R989.2 R990.2 R991.2 R992.2 R1040.1 R1041.1 R1068.2 R1069.2 R1073.2 R1074.2 R1081.2 R1082.2 R1084.1 R1098.2 R1099.2 R1100.2 R1101.2 R1103.2 R1104.2 R1107.1 R1111.2 R1133.2 SW502.3 SW502.4 U15.3(GND) U15.8(GND) U16.3(GND) U16.8(GND) U17.3(GND) U17.8(GND) U22.3(GND) U22.8(GND) U31.8(GND) U36.29(GND) U1003.4(VSS) U1004.A1(VSS) U1004.A14(VSS) U1004.B6(VSS) U1004.B7(VSS) U1004.B8(VSS) U1004.B9(VSS) U1004.D3(VSS) U1004.D4(VSS) U1004.D5(VSS) U1004.D7(VSS) U1004.D8(VSS) U1004.D10(VSS) U1004.D11(VSS) U1004.D12(VSS) U1004.F6(VSS) U1004.F7(VSS) U1004.F8(VSS) U1004.F9(VSS) U1004.G6(VSS) U1004.G7(VSS) U1004.G8(VSS) U1004.G9(VSS) U1004.H6(VSS) U1004.H7(VSS) U1004.H8(VSS) U1004.H9(VSS) U1004.J6(VSS) U1004.J7(VSS) U1004.J8(VSS) U1004.J9(VSS) U1004.L3(VSS) U1004.L4(VSS) U1004.L6(VSS) U1004.L7(VSS) U1004.L8(VSS) U1004.L9(VSS) U1004.L11(VSS) U1004.L12(VSS) U1004.M7(VSS) U1004.M8(VSS) U1004.P1(VSS) U1004.P14(VSS) U1006.1(GND1) U1006.5(GND5) U1006.10(AGND) U1006.11(GND11) U1006.15(GND15) U1006.25(GND25) U1006.35(GND35) U1006.47(GND47) U1006.51(GND51) U1011.2(GND) U1014.3(GND) U1014.8(GND) U1015.1(GND) U1016.3(GND) U1016.8(GND) U1017.3(GND) U1017.8(GND) U1018.3(GND) U1018.8(GND) U1021.B3(GND) U1021.B6(GND) U1021.D4(GND) U1021.D5(GND) U1021.D8(TEST) U1021.E4(GND) U1021.E5(GND) U1021.G3(GND) U1021.G6(GND) U1022.4(VSS) U1024.5(GND) U1024.6(SHLD4) U1024.7(SHLD3) U1024.8(SHLD2) U1024.9(SHLD1) U1024.10(SHLD5) U1024.11(SHLD6) Y501.2 Y501.4 Y502.2 Y502.4 Y504.2 Y504.4 ; also on sheet 3 4 5 6 7 8 9 10 11 12
VBUS_PORT1: R1013.2 R1020.2 ; also on sheet 4 5 7 8
VBUS_UPSTREAM: C37.1 C851.1 C852.1 C853.1 J28.A4(VBUS1) J28.A9(VBUS2) J28.B4(VBUS3) J28.B9(VBUS4) ; also on sheet 5
4_2_LANE_MODE: R1137.1 SW504.2 ; also on sheet 5 12
460_EN: U36.17(EN) ; also on sheet 5 6 12
2850_SPI_CLK: U1021.D2(SPI_CLK) U1022.6(SPI_CLK)
2850_SPI_CSN: U1021.C1(SPI_CSN) U1022.1(/CE)
2850_SPI_DI: U1021.C2(SPI_DI) U1022.2(SPI_DO)
2850_SPI_DO: U1021.D1(SPI_DO) U1022.5(SPI_DI)
2850_SPI_WP: R1104.1 U1021.E2(SPI_WP) U1022.3(/WP)
+1P2V_A2850: C896.2 C897.2 C901.1 C902.1 C903.1 C904.1 FB606.2 U1021.B4(VDD12_RX) U1021.B5(VDD12_RX) U1021.B7(AVDD12_PLL) U1021.F4(VDD12_OSC) U1021.G5(VDD12_TX) U1021.G7(VDD12_TX)
+3P3V_A2850: C907.1 C908.1 C910.1 FB607.2 U1021.B2(VDD33_RX) U1021.C4(VDD33_RX) U1021.G2(VDD33_TX) U1021.G4(VDD33_TX)
AMSEL: U36.8(AMSEL) U1004.E12(GPIO8) ; also on sheet 5
AUX_N: C894.2 R1068.1 U1004.L10(GPIO4) ; also on sheet 5
AUX_P: C893.2 R1067.2 U1004.L5(GPIO3) ; also on sheet 5
AUXN0: C811.1 J33.18(AUX_CHN) R811.2 U1016.5(D2-) U1016.6(NC6)
AUXP0: C810.1 J33.16(AUX_CHP) R812.1 U1016.4(D2+) U1016.7(NC7)
BOARD_1P2V: C628.1 C629.1 C631.1 C632.1 C635.1 C636.1 C651.1 C652.1 C898.1 C899.1 C900.1 FB601.1 FB606.1 R1089.1 U1004.E5(DVDD12) U1004.E10(DVDD12) U1004.F5(DVDD12) U1004.F10(DVDD12) U1004.G5(DVDD12) U1004.G10(DVDD12) U1004.H5(DVDD12) U1004.H10(DVDD12) U1021.D6(VDD12_DIG) U1021.F5(VDD12_DIG) ; also on sheet 4 6
BOARD_3P3V: C11.1 C12.1 C14.1 C503.1 C513.2 C514.2 C609.2 C611.1 C616.2 C622.1 C655.1 C812.2 C813.2 C820.2 C869.1 C870.1 C871.1 C872.1 C876.1 C877.1 C878.1 C879.1 C884.1 C905.1 C914.1 D832.2(ANODE) FB604.1 FB607.1 R503.1 R504.1 R505.1 R507.1 R701.1 R703.1 R705.1 R707.1 R709.1 R711.1 R713.1 R715.1 R716.1 R811.1 R820.1 R823.1 R825.1 R826.1 R827.1 R903.1 R904.2 R909.2 R1014.2 R1016.2 R1021.2 R1023.2 R1083.2 R1102.1 R1105.1 R1106.1 R1132.1 U36.22(VCC) U1003.8(VCC) U1004.J5(DVDD33) U1004.J10(DVDD33) U1004.L14(AVDD33_RCOSC) U1006.4(VPHY) U1006.9(VPLL) U1006.20(VCCIO20) U1006.31(VCCIO31) U1006.42(VCCIO42) U1006.50(VREGIN) U1006.56(VCCIO56) U1011.6(VCC) U1015.2(IN2) U1015.3(IN3) U1021.C5(VDD33_AUX) U1021.D3(VDD33_IO) U1021.E3(VDD33_IO) U1022.8(VCC) ; also on sheet 3 4 5 6 7 8 9 10 11 12
BOARD_5V: C814.2 C815.2 ; also on sheet 3 5 8 9 11
BOARD_A1P2V: C502.2 C507.2 C601.1 C602.1 C603.1 C605.1 C606.1 C612.2 C613.2 C614.2 C620.2 C621.2 C650.1 FB601.2 R502.1 R508.1 U1004.C5(AVDD12_RX) U1004.C6(AVDD12_RX) U1004.C9(AVDD12_RX) U1004.C10(AVDD12_RX) U1004.K13(AVDD12_PLL) U1004.L13(AVDD12_OSC1) U1004.M2(AVDD12_TX0) U1004.M5(AVDD12_TX0) U1004.M6(AVDD12_OSC0) U1004.M10(AVDD12_TX1) U1004.N9(AVDD12_TX1)
BOARD_A3P3V: C501.2 C520.2 C608.1 C615.1 C617.1 C623.1 C624.2 C637.2 FB604.2 R501.1 R510.1 R1067.1 U1004.C2(AVDD33_RX) U1004.C7(AVDD33_RX) U1004.C8(AVDD33_RX) U1004.C13(AVDD33_RX) U1004.M13(AVDD33_TX1) U1004.N6(AVDD33_TX0)
BS_1: R703.2 R704.2 U1004.F2(GPO/BS1)
C_UART_RX: R994.1 R996.1 U1006.39(CDBUS1)
C_UART_TX: R993.1 R995.1 U1006.38(CDBUS0)
CC1_65986: J28.A5(CC1) U16.2(D1-) U16.9(NC9) ; also on sheet 5
CC2_65986: J28.B5(CC2) U15.4(D2+) U15.7(NC7) ; also on sheet 5
CSBU1: J28.A8(SBU1) R48.1 R203.1 U15.5(D2-) U15.6(NC6)
CSBU1_65986: R203.2 ; also on sheet 5
CSBU2: J28.B8(SBU2) R56.1 R205.1 U16.1(D1+) U16.10(NC10)
CSBU2_65986: R205.2 ; also on sheet 5
D_UART_RX: R991.1 U1006.52(DDBUS1)
D_UART_TX: R992.1 U1006.48(DDBUS0)
DM_UP: J28.A7(DN1) J28.B7(DN2) U17.4(D2+) U17.7(NC7) ; also on sheet 6
DP_MODE_LED: R1015.2 R1019.1 R1022.2 R1025.1 ; also on sheet 5
DP_POWER: C809.1 D805.1(CATHODE) J33.20(DP_PWR) U1015.5(OUT5) U1015.6(OUT6) U1015.7(OUT7) U1015.8(OUT8)
DP_UP: J28.A6(DP1) J28.B6(DP2) U17.5(D2-) U17.6(NC6) ; also on sheet 6
DPRX0_HPD_OUT: R1129.1 ; also on sheet 5
DPTX0_AUXN: C811.2 U1004.M1(TX0_AUX_N)
DPTX0_AUXP: C810.2 U1004.N1(TX0_AUX_P)
DPTX0_CONFIG1: J33.4(CONFIG_1) R805.1 U1004.K3(GPIO0) U1018.4(D2+) U1018.7(NC7)
DPTX0_CONFIG2: J33.6(CONFIG_2) R806.1 U1004.K4(GPIO1) U1018.5(D2-) U1018.6(NC6)
DPTX0_HPD_IN: J33.2(HOT_DET) R804.1 R1128.2 U1018.2(D1-) U1018.9(NC9)
DPTX0_L0N: C802.1 J33.5(ML_LANE_0N) U1014.5(D2-) U1014.6(NC6)
DPTX0_L0P: C801.1 J33.3(ML_LANE_0P) U1014.4(D2+) U1014.7(NC7)
DPTX0_L1N: C804.1 J33.11(ML_LANE_1N) U1017.2(D1-) U1017.9(NC9)
DPTX0_L1P: C803.1 J33.9(ML_LANE_1P) U1017.1(D1+) U1017.10(NC10)
DPTX0_L2N: C806.1 J33.17(ML_LANE_2N) U1017.5(D2-) U1017.6(NC6)
DPTX0_L2P: C805.1 J33.15(ML_LANE_2P) U1017.4(D2+) U1017.7(NC7)
DPTX0_L3N: C808.1 J33.12(ML_LANE_3N) U1016.2(D1-) U1016.9(NC9)
DPTX0_L3P: C807.1 J33.10(ML_LANE_3P) U1016.1(D1+) U1016.10(NC10)
DPTX0_ML_L0N: C802.2 U1004.P6(TX0_LN0_N)
DPTX0_ML_L0P: C801.2 U1004.P7(TX0_LN0_P)
DPTX0_ML_L1N: C804.2 U1004.N5(TX0_LN1_N)
DPTX0_ML_L1P: C803.2 U1004.P5(TX0_LN1_P)
DPTX0_ML_L2N: C806.2 U1004.M3(TX0_LN2_N)
DPTX0_ML_L2P: C805.2 U1004.M4(TX0_LN2_P)
DPTX0_ML_L3N: C808.2 U1004.P2(TX0_LN3_N)
DPTX0_ML_L3P: C807.2 U1004.N2(TX0_LN3_P)
DPTX1_AUXN: C911.1 R1073.1 U1004.P8(TX1_AUX_N)
DPTX1_AUXP: C912.1 R1074.1 U1004.P9(TX1_AUX_P)
DPTX1_CONFIG1: R1040.2 U1004.H1(GPIO12)
DPTX1_CONFIG2: R1041.2 U1004.G3(GPIO13)
DPTX1_D0N: U1004.N14(TX1_LN0_N) U1021.A7(DPRX_L0N)
DPTX1_D0P: U1004.M14(TX1_LN0_P) U1021.A8(DPRX_L0P)
DPTX1_D1N: U1004.N13(TX1_LN1_N) U1021.A5(DPRX_L1N)
DPTX1_D1P: U1004.P13(TX1_LN1_P) U1021.A6(DPRX_L1P)
DPTX1_D2N: U1004.M11(TX1_LN2_N) U1021.A3(DPRX_L2N)
DPTX1_D2P: U1004.M12(TX1_LN2_P) U1021.A4(DPRX_L2P)
DPTX1_D3N: U1004.P10(TX1_LN3_N) U1021.A1(DPRX_L3N)
DPTX1_D3P: U1004.N10(TX1_LN3_P) U1021.A2(DPRX_L3P)
DPTX1_HPD: R1130.2 U1021.B1(DPRX_HPD_OUT)
EECLK_FTDI: R826.2 U1006.62(EECLK) U1011.4(CLK)
EECS_FTDI: R825.2 U1006.63(EECS) U1011.5(CS)
EEDATA_FTDI: R827.2 R1004.2 U1006.61(EEDATA) U1011.3(DI)
FTDI_TN: R874.2 R876.2 U1006.7(DM) U1024.2(D-)
FTDI_TP: R873.2 R875.2 U1006.8(DP) U1024.3(D+)
GPIO_A0: R990.1 U1006.21(ADBUS4)
GPIO_A1: R989.1 U1006.22(ADBUS5)
GPIO_A2: R988.1 U1006.23(ADBUS6)
GPIO_A3: R987.1 U1006.24(ADBUS7)
GPIO_B0: R986.1 U1006.30(BDBUS4)
GPIO_B1: R985.1 U1006.32(BDBUS5)
GPIO_B2: R984.1 U1006.33(BDBUS6)
GPIO_B3: R983.1 U1006.34(BDBUS7)
HD1: R1090.1 U1021.H4(HDMITX_CH0P)
HD2: R1091.1 U1021.H3(HDMITX_CH0N)
HD3: R1092.1 U1021.H6(HDMITX_CH1P)
HD4: R1093.1 U1021.H5(HDMITX_CH1N)
HD5: R1094.1 U1021.H8(HDMITX_CH2P)
HD6: R1095.1 U1021.H7(HDMITX_CH2N)
HD7: R1096.1 U1021.H2(HDMITX_CLKP)
HD8: R1097.1 U1021.H1(HDMITX_CLKN)
HDMI_5V_CON: C868.1 D833.2(ANODE) D834.2(ANODE) P2.18(5Vcc) U31.6(5V_OUT)
HDMI_CEC: R520.2 U1004.E3(HDMI_CEC)
HDMI_CEC_SNK: P2.13(CEC) R832.1 R833.2 U31.1(CTRL1) U1021.F2(HDMI_CEC)
HDMI_D0N: P2.9(TX0n) R1091.2 U31.11(D2-)
HDMI_D0P: P2.7(TX0p) R1090.2 U31.12(D2+)
HDMI_D1N: P2.6(TX1n) R1093.2 U31.13(D1-)
HDMI_D1P: P2.4(TX1p) R1092.2 U31.14(D1+)
HDMI_D2N: P2.3(TX2n) R1095.2 U31.15(D0-)
HDMI_D2P: P2.1(TX2p) R1094.2 U31.16(D0+)
HDMI_D3N: P2.12(TXCn) R1097.2 U31.9(D3-)
HDMI_D3P: P2.10(TXCp) R1096.2 U31.10(D3+)
HDMI_DDC_SCL: P2.15(TSCL) R1080.2 U31.2(CTRL2) U1021.E1(HDMITX_DDC_SCL)
HDMI_DDC_SDA: P2.16(TSDA) R1079.2 U31.3(CTRL3) U1021.F1(HDMITX_DDC_SDA)
HDMI_TX0_DCC_SCL: R1081.1 U1004.D13(HDMI_TX0_DDC_SCL)
HDMI_TX0_DCC_SDA: R1082.1 U1004.D14(HDMI_TX0_DDC_SDA)
HPD_HDMI_CON: P2.19(HPD) R1111.1 R1138.2 U31.4(CTRL4)
HPD_SRC: R1138.1 U1021.G1(HDMITX_HPD_IN)
I2C_IRQ_86: R898.1 ; also on sheet 5 11
I2C_IRQ_DBG: R898.2 R1002.2
I2C_SCL_DBG: J17.1 R901.2 R908.2 U1006.26(BDBUS0)
I2C_SCL_MAIN: R715.2 R901.1 U1004.J12(HOST_I2C_SCL) ; also on sheet 5 11 12
I2C_SDA_DBG: J17.3 R897.2 R907.1 U1006.27(BDBUS1) U1006.28(BDBUS2)
I2C_SDA_MAIN: R716.2 R897.1 U1004.K14(HOST_I2C_SDA) ; also on sheet 5 11 12
ML0N: U36.18(LNBN) U1004.B5(RX0_LN0_N)
ML0P: U36.19(LNBP) U1004.A5(RX0_LN0_P)
ML1N: U36.15(LNAN) U1004.C3(RX0_LN1_N)
ML1P: U36.16(LNAP) U1004.C4(RX0_LN1_P)
ML2N: U36.23(LNDN) U1004.A2(RX0_LN2_N)
ML2P: U36.24(LNDP) U1004.B2(RX0_LN2_P)
ML3N: U36.20(LNCN) U1004.C1(RX0_LN3_N)
ML3P: U36.21(LNCP) U1004.B1(RX0_LN3_P)
MST_4_2_LN_MD: R1137.2 U1004.E13(GPIO6)
MST_GPIO_DP_LED#: R1024.2 R1026.1 U1004.F11(GPIO9)
MST_GPIO_HDMI_LED#: R1017.2 R1018.1 U1004.F12(GPIO10)
POL: U36.3(POL) ; also on sheet 5
RESETn: C504.2 R503.2 SW502.1 SW502.2 U1004.H12(RESET_n)
S/PDIF_OUT0: R709.2 R710.2 U1004.E2(S/PDIF_OUT0/BS4)
S/PDIF_OUT1: R713.2 R714.2 U1004.F3(S/PDIF_OUT1/BS6)
SBU1_460: R910.2 U36.13(SBU1)
SBU2_460: R911.2 U36.14(SBU2)
SPI_CLK: R705.2 R706.2 R1065.2 U1004.H3(SPI_CLK/BS2)
SPI_CLK_86: J17.7 R997.1 U1006.16(ADBUS0) ; also on sheet 5
SPI_CSn: R711.2 R712.2 R1063.1 U1004.J3(SPI_CSn/BS5)
SPI_DI: R1064.1 U1004.J1(SPI_DI)
SPI_DO: R707.2 R708.2 R1066.2 U1004.K2(SPI_DO/BS3)
SPI_MISO_86: J17.5 R1001.2 U1006.18(ADBUS2) ; also on sheet 5
SPI_MOSI_86: J17.8 R998.1 R1003.2 U1006.17(ADBUS1) ; also on sheet 5
SPI_SS_86: J17.9 R999.1 U1006.19(ADBUS3) ; also on sheet 5
SSRXM_UP: U36.28(SSRXP) ; also on sheet 6
SSRXN1: J28.B10(SSRXN1) U22.4(D2+) U22.7(NC7) U36.2(CRX1N)
SSRXN2: J28.A10(SSRXN2) U15.2(D1-) U15.9(NC9) U36.10(CRX2N)
SSRXP1: J28.B11(SSRXP1) U22.5(D2-) U22.6(NC6) U36.1(CRX1P)
SSRXP2: J28.A11(SSRXP2) U15.1(D1+) U15.10(NC10) U36.9(CRX2P)
SSRXP_UP: U36.27(SSRXN) ; also on sheet 6
SSTXM_UP: U36.26(SSTXP) ; also on sheet 6
SSTXN1: C3.1 J28.A3(SSTXN1) R940.2 U16.4(D2+) U16.7(NC7)
SSTXN1_460: C3.2 U36.5(CTX1N)
SSTXN2: C8.1 J28.B3(SSTXN2) R938.2 U17.2(D1-) U17.9(NC9)
SSTXN2_460: C8.2 U36.7(CTX2N)
SSTXP1: C2.1 J28.A2(SSTXP1) R941.2 U16.5(D2-) U16.6(NC6)
SSTXP1_460: C2.2 U36.4(CTX1P)
SSTXP2: C7.1 J28.B2(SSTXP2) R939.2 U17.1(D1+) U17.10(NC10)
SSTXP2_460: C7.2 U36.6(CTX2P)
SSTXP_UP: U36.25(SSTXN) ; also on sheet 6
SWD_CLK_82: R872.1 ; also on sheet 11
SWD_CLK_86: R870.1 ; also on sheet 5
SWD_CLK_DEBUG: R870.2 R872.2 R906.1 R1084.2
SWD_DATA_82: R871.1 ; also on sheet 11
SWD_DATA_86: R869.1 ; also on sheet 5
SWD_DATA_DEBUG: R869.2 R871.2 R905.1 R1083.1
TX1_DDC_SCL: R1099.1 U1004.E14(HDMI_TX1_DDC_SCL)
TX1_DDC_SDA: R1098.1 U1004.E11(HDMI_TX1_DDC_SDA)
UART_RX: J7.2 R507.2 U1004.J2(UART_RX)
UART_RX_86: R995.2 R996.2 R1000.2 ; also on sheet 5 11
UART_RX_2850: J32.2 R1102.2 U1021.E7(UART_RX)
UART_TX: J7.1 R701.2 R702.2 U1004.H4(UART_TX/BS0)
UART_TX_86: R993.2 R994.2 R1003.1 ; also on sheet 5 11
UART_TX_2850: J32.1 U1021.D7(UART_TX)
USB_TN_FTDI: R876.1 ; also on sheet 5
USB_TN_FTDI_82: R874.1 ; also on sheet 11
USB_TP_FTDI: R875.1 ; also on sheet 5
USB_TP_FTDI_82: R873.1 ; also on sheet 11
VREGOUT: C873.1 C874.1 C875.1 U1006.12(VCORE12) U1006.37(VCORE37) U1006.49(VREGOUT) U1006.64(VCORE64)
N16856603: R502.2 U1004.L2(TX0_REXT)
N16856785: R513.1 U1004.D2(TEST)
N16856863: R510.2 U1004.D9(RX1_REXT)
N16856966: R508.2 U1004.M9(TX1_REXT)
N16857185: R501.2 U1004.D6(RX0_REXT)
N16857243: C509.1 U1004.N8(XTAL) Y501.3
N16857247: C510.2 U1004.N7(TCLK) Y501.1
N16857403: R505.2 U1003.7(/HOLD)
N16857410: R504.2 U1003.3(/WP)
N16859516: C627.1 U1004.K5(DVDD25_SM)
N16860977: R977.2 U1004.H2(HOST_IRQ_OUT)
N16862935: R820.2 U1015.4(EN)
N16878349: R822.1 U1006.6(REF)
N16878379: R823.2 U1006.14(RESET#)
N16878466: C822.1 U1006.2(OSCI) Y502.1
N16878473: C821.1 U1006.3(OSCO) Y502.3
N16878549: R824.1 U1006.13(TEST)
N16978836: J22.1 R903.2
N16979037: J22.7 R905.2
N16979046: J22.9 R906.2
N16979348: J22.2 R904.1
N16979664: J23.1 R907.2
N16979925: J23.2 R908.1
N16979931: J23.6 R909.1
N17083393: R978.1 U1004.F13(GPIO11)
N17087543: J23.3 R997.2
N17087576: J23.7 R998.2
N17087579: J23.9 R999.2
N17087723: J23.4 R1002.1
N17090571: J23.8 R1001.1
N17090574: J23.10 R1000.1
N17091700: R1004.1 U1011.1(DO)
N17167099: D829.2(ANODE) R1013.1
N17167118: Q22.2(B) R1015.1 R1017.1
N17167120: D829.1(CATHODE) Q22.3(C)
N17167126: D830.2(ANODE) R1014.1
N17167151: Q16.3(DRAIN) Q21.2(B) R1016.1
N17169990: D827.2(ANODE) R1020.1
N17170000: Q31.2(B) R1022.1 R1024.1
N17170011: D827.1(CATHODE) Q31.3(C)
N17170031: Q19.3(DRAIN) Q30.2(B) R1023.1
N17209999: D828.2(ANODE) R1021.1
N17210003: D828.1(CATHODE) Q30.3(C)
N17210303: D830.1(CATHODE) Q21.3(C)
N17211446: R1069.1 U1004.F14(GPIO7)
N17211589: Q19.1(GATE) R1025.2 R1026.2
N17211900: Q16.1(GATE) R1018.2 R1019.2
N17285937: R1063.2 U1003.1(/CE)
N17285940: R1064.2 U1003.2(SPI_DO)
N17285959: R1065.1 U1003.6(SPI_CLK)
N17285962: R1066.1 U1003.5(SPI_DI)
N17292278: C893.1 U1004.A6(RX0_AUX_P)
N17292287: C894.1 U1004.A7(RX0_AUX_N)
N17354176: C897.1 U1021.E8(XTAL) Y504.3
N17354267: C896.1 U1021.F8(TCLK) Y504.1
N17357818: C911.2 U1021.C8(DPRX_AUXN)
N17357821: C912.2 U1021.C7(DPRX_AUXP)
N17358533: R1089.2 U1021.C6(R_EXT)
N17358602: C913.1 U1021.F7(C_EXT)
N17359544: R1100.1 U1021.F6(I2C_SCL)
N17359547: R1101.1 U1021.E6(I2C_SDA)
N17360371: R1103.1 U1021.C3(GPIO1)
N17360674: R1105.2 U1022.7(/HOLD)
N17361374: C915.1 R1106.2 U1021.B8(RESETN)
N17361689: R1107.2 U1021.F3(CONFIG1)
N17406609: D832.1(CATHODE) R833.1
N17406845: D833.1(CATHODE) R1080.1
N17406848: D834.1(CATHODE) R1079.1
N17511445: R1128.1 U1004.E4(TX0_HPD)
N17511457: R1130.1 U1004.D1(TX1_HPD)
N17511466: R1129.2 U1004.F4(RX0_HPD)
N17571762: R1133.1 SW504.3
N17571792: R1132.2 SW504.1

Not connected (* = marked no-connect by the designer): J17 4 6; J22 3* 5*; P2 14(GND5)*; U22 1(D1+)* 2(D1-)* 9(NC9)* 10(NC10)*; U31 7(CTRL5)*; U36 11(CSBU1)* 12(CSBU2)*; U1004 A8(RX1_LN3_N)* A9(RX1_LN3_P)* A10(RX1_LN2_N)* A13(RX1_LN0_P)* B10(RX1_LN2_P)* B13(RX1_LN0_N)* B14(RX1_AUX_N)* C11(RX1_LN1_N)* C12(RX1_LN1_P)* C14(RX1_AUX_P)* E1(RX1_HPD)* F1(MASTER1_IRQ_IN)* G1(MASTER2_IRQ_IN)* G2(MASTER3_IRQ_IN)* G4(MASTER0_IRQ_IN)* G11(MASTER2_I2C_SDA)* G12(MASTER2_I2C_SCL)* G13(MASTER0_I2C_SDA)* G14(MASTER0_I2C_SCL)* H11(HDMI_RX0_DDC_SCL)* H13(MASTER1_I2C_SDA)* H14(MASTER1_I2C_SCL)* J4(GPIO2)* J11(HDMI_RX1_DDC_SCL)* J13(MASTER3_I2C_SCL)* J14(MASTER3_I2C_SDA)* K1(TCLK_3V3_OUT)* K10(GPIO5)* K11(HDMI_RX1_DDC_SDA)* K12(HDMI_RX0_DDC_SDA)* L1(TCLK_1V2_OUT)*; U1006 29(BDBUS3)* 36(SUSPEND#)* 40(CDBUS2)* 41(CDBUS3)* 43(CDBUS4)* 44(CDBUS5)* 45(CDBUS6)* 46(CDBUS7)* 53(DDBUS2)* 54(DDBUS3)* 55(DDBUS4)* 57(DDBUS5)* 58(DDBUS6)* 59(DDBUS7)* 60(PWREN#)*; U1014 1(D1+)* 2(D1-)* 9(NC9)* 10(NC10)*; U1018 1(D1+)* 10(NC10)*; U1021 G8(VDD12_ON)*; U1024 1(VBUS)* 4(ID)*

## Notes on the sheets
sheet 13
- STDP4320
- TO/FROM HD3SS460
- DISPLAYPORT
- TO DP/HDMI
  CONVERTER
- For DEBUG ONLY
sheet 14
- STDP4320 POWER
sheet 15
- STDP4320 BOOTSTRAPS
- (BS_0)
- (BS_1)
- (BS_2)
- (BS_3)
- (BS_4)
- (BS_5)
- (BS_6)
- STDP4320 Hardware BootStraps
- 2 LANE - 4 LANE SWTICH
sheet 16
- DISPLAYPORT
- mDP LEDS
sheet 17
- DP TO HDMI CONVERTER
- RIGHT ANGLE
  HEADER
- BOBCAT
sheet 18
- ESD PROTECTION FOR HDMI
- CURRENT LIMITS 5V TO 55mA
- HDMI TX
- HDMI Sink Connection
- SPDIF
- HDMI LEDS
sheet 19
- DEBUG BOARD - FTDI - USB - I2C/SPI/UART
- AARDVARK
- FROM TPS65986
- FROM TPS65986
- USB2ANY
- FROM TPS65982
- FROM TPS65986
- FROM TPS65982
- NOTE #11
- ULINK2 DEBUGGER
sheet 20
- USB TYPE C FRONT END
- INPUTS FROM TPS65986
- Type C Connector
- TypeC Connector Pin Mapping
- TO/FROM TUSB8041
- GND
- GND
- A1
- B12
- SSTXP1
- A2
- SSRXP1
- SSTXP2
- B11
- SSRXP2
- TO MST HUB
- SSTXN1
- SSTXN2
- A3
- B10
- SSRXN1
- SSRXN1
- VBUS
- VBUS
- A4
- B9
- TO/FROM TUSB8041
- CC1
- A5
- B8
- SBU2
- DP1
- DN2
- A6
- B7
- DN1
- A7
- B6
- DP2
- SBU1
- CC2
- A8
- B5
- VBUS
- A9
- B4
- VBUS
- NOTE #2
- SSRXN2
- SSTXN2
- SSRXN1
- A10
- B3
- SSTXN1
- SSRXP2
- A11
- B2
- SSTXP2
- SSRXP1
- SSTXP1
- GND
- GND
- A12
- B1
- NOTE: ALL DIFF PAIRS ARE
  ROUTED 85 TO 90 OHMS
  DIFFERENTIAL AND 50 OHMS
  COMMON MODE. ALL OTHER
  TRACES ARE 50 OHM.
- NOTE #3
- NOTE #4
